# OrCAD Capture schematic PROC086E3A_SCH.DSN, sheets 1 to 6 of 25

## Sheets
1 25. HARDWARE SCHEMATICS: title: HARDWARE SCHEMATICS; rev: E3A
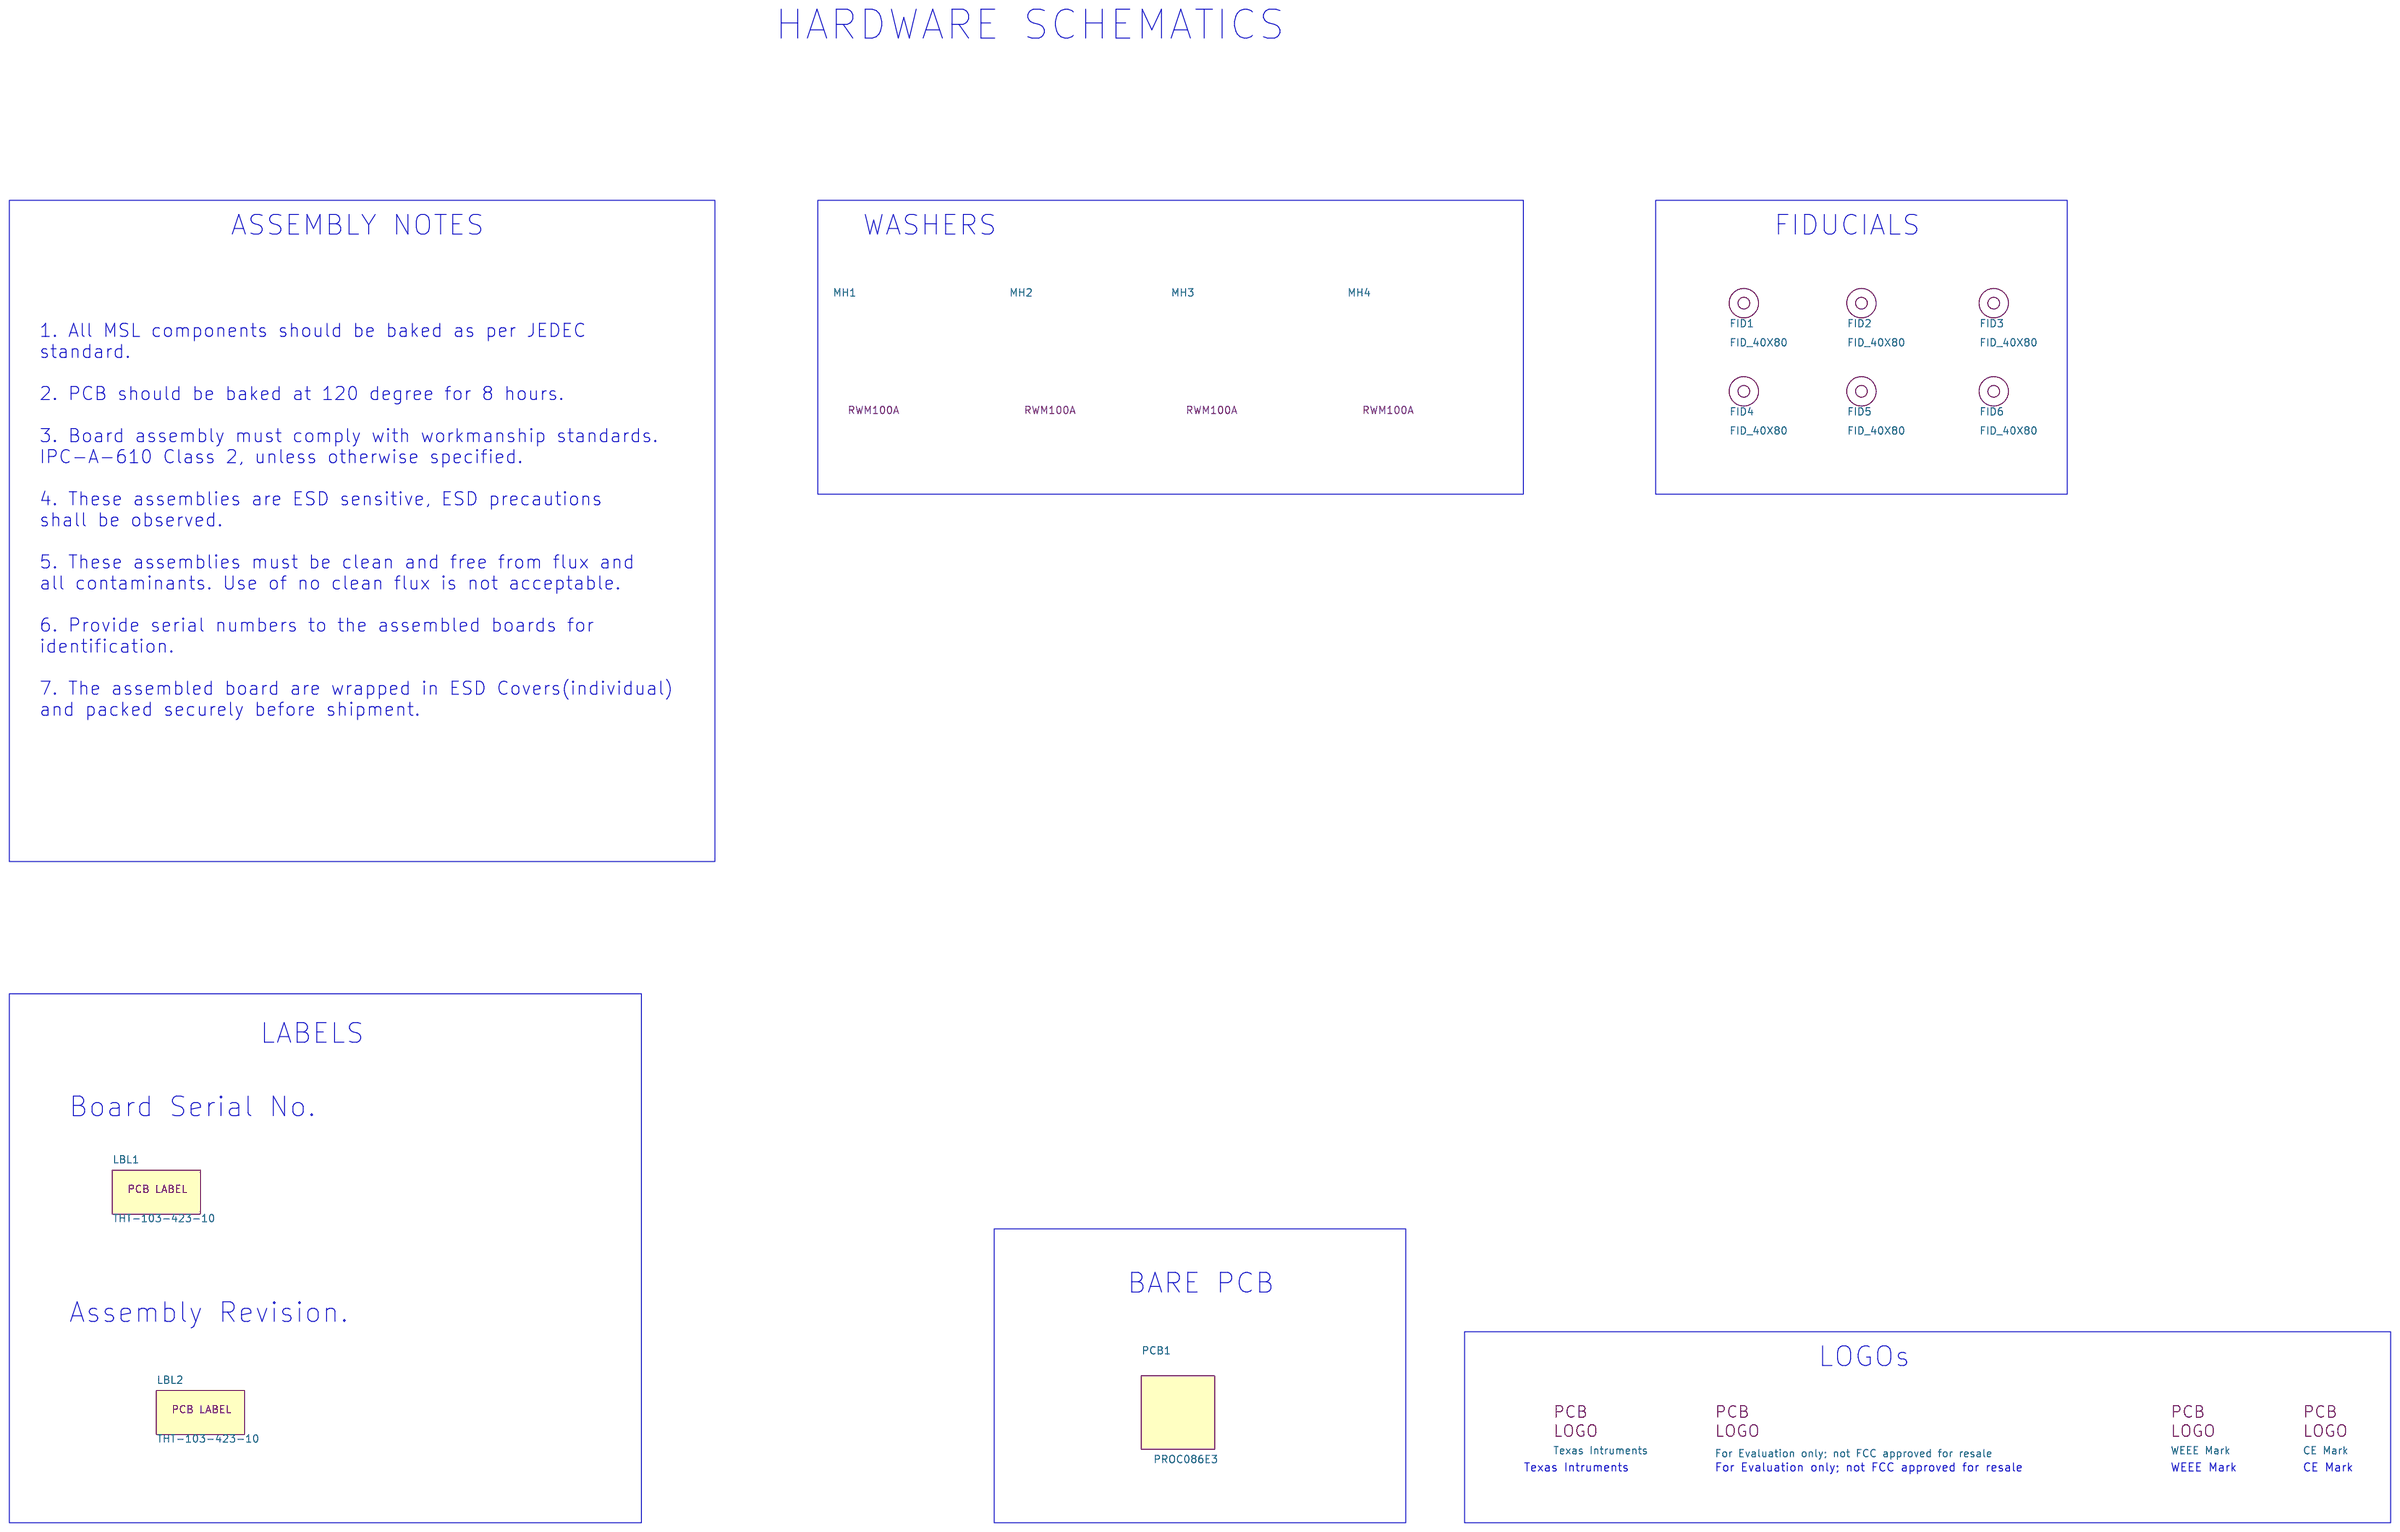
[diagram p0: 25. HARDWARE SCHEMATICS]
2 01. TABLE OF CONTENTS: title: TABLE OF CONTENTS
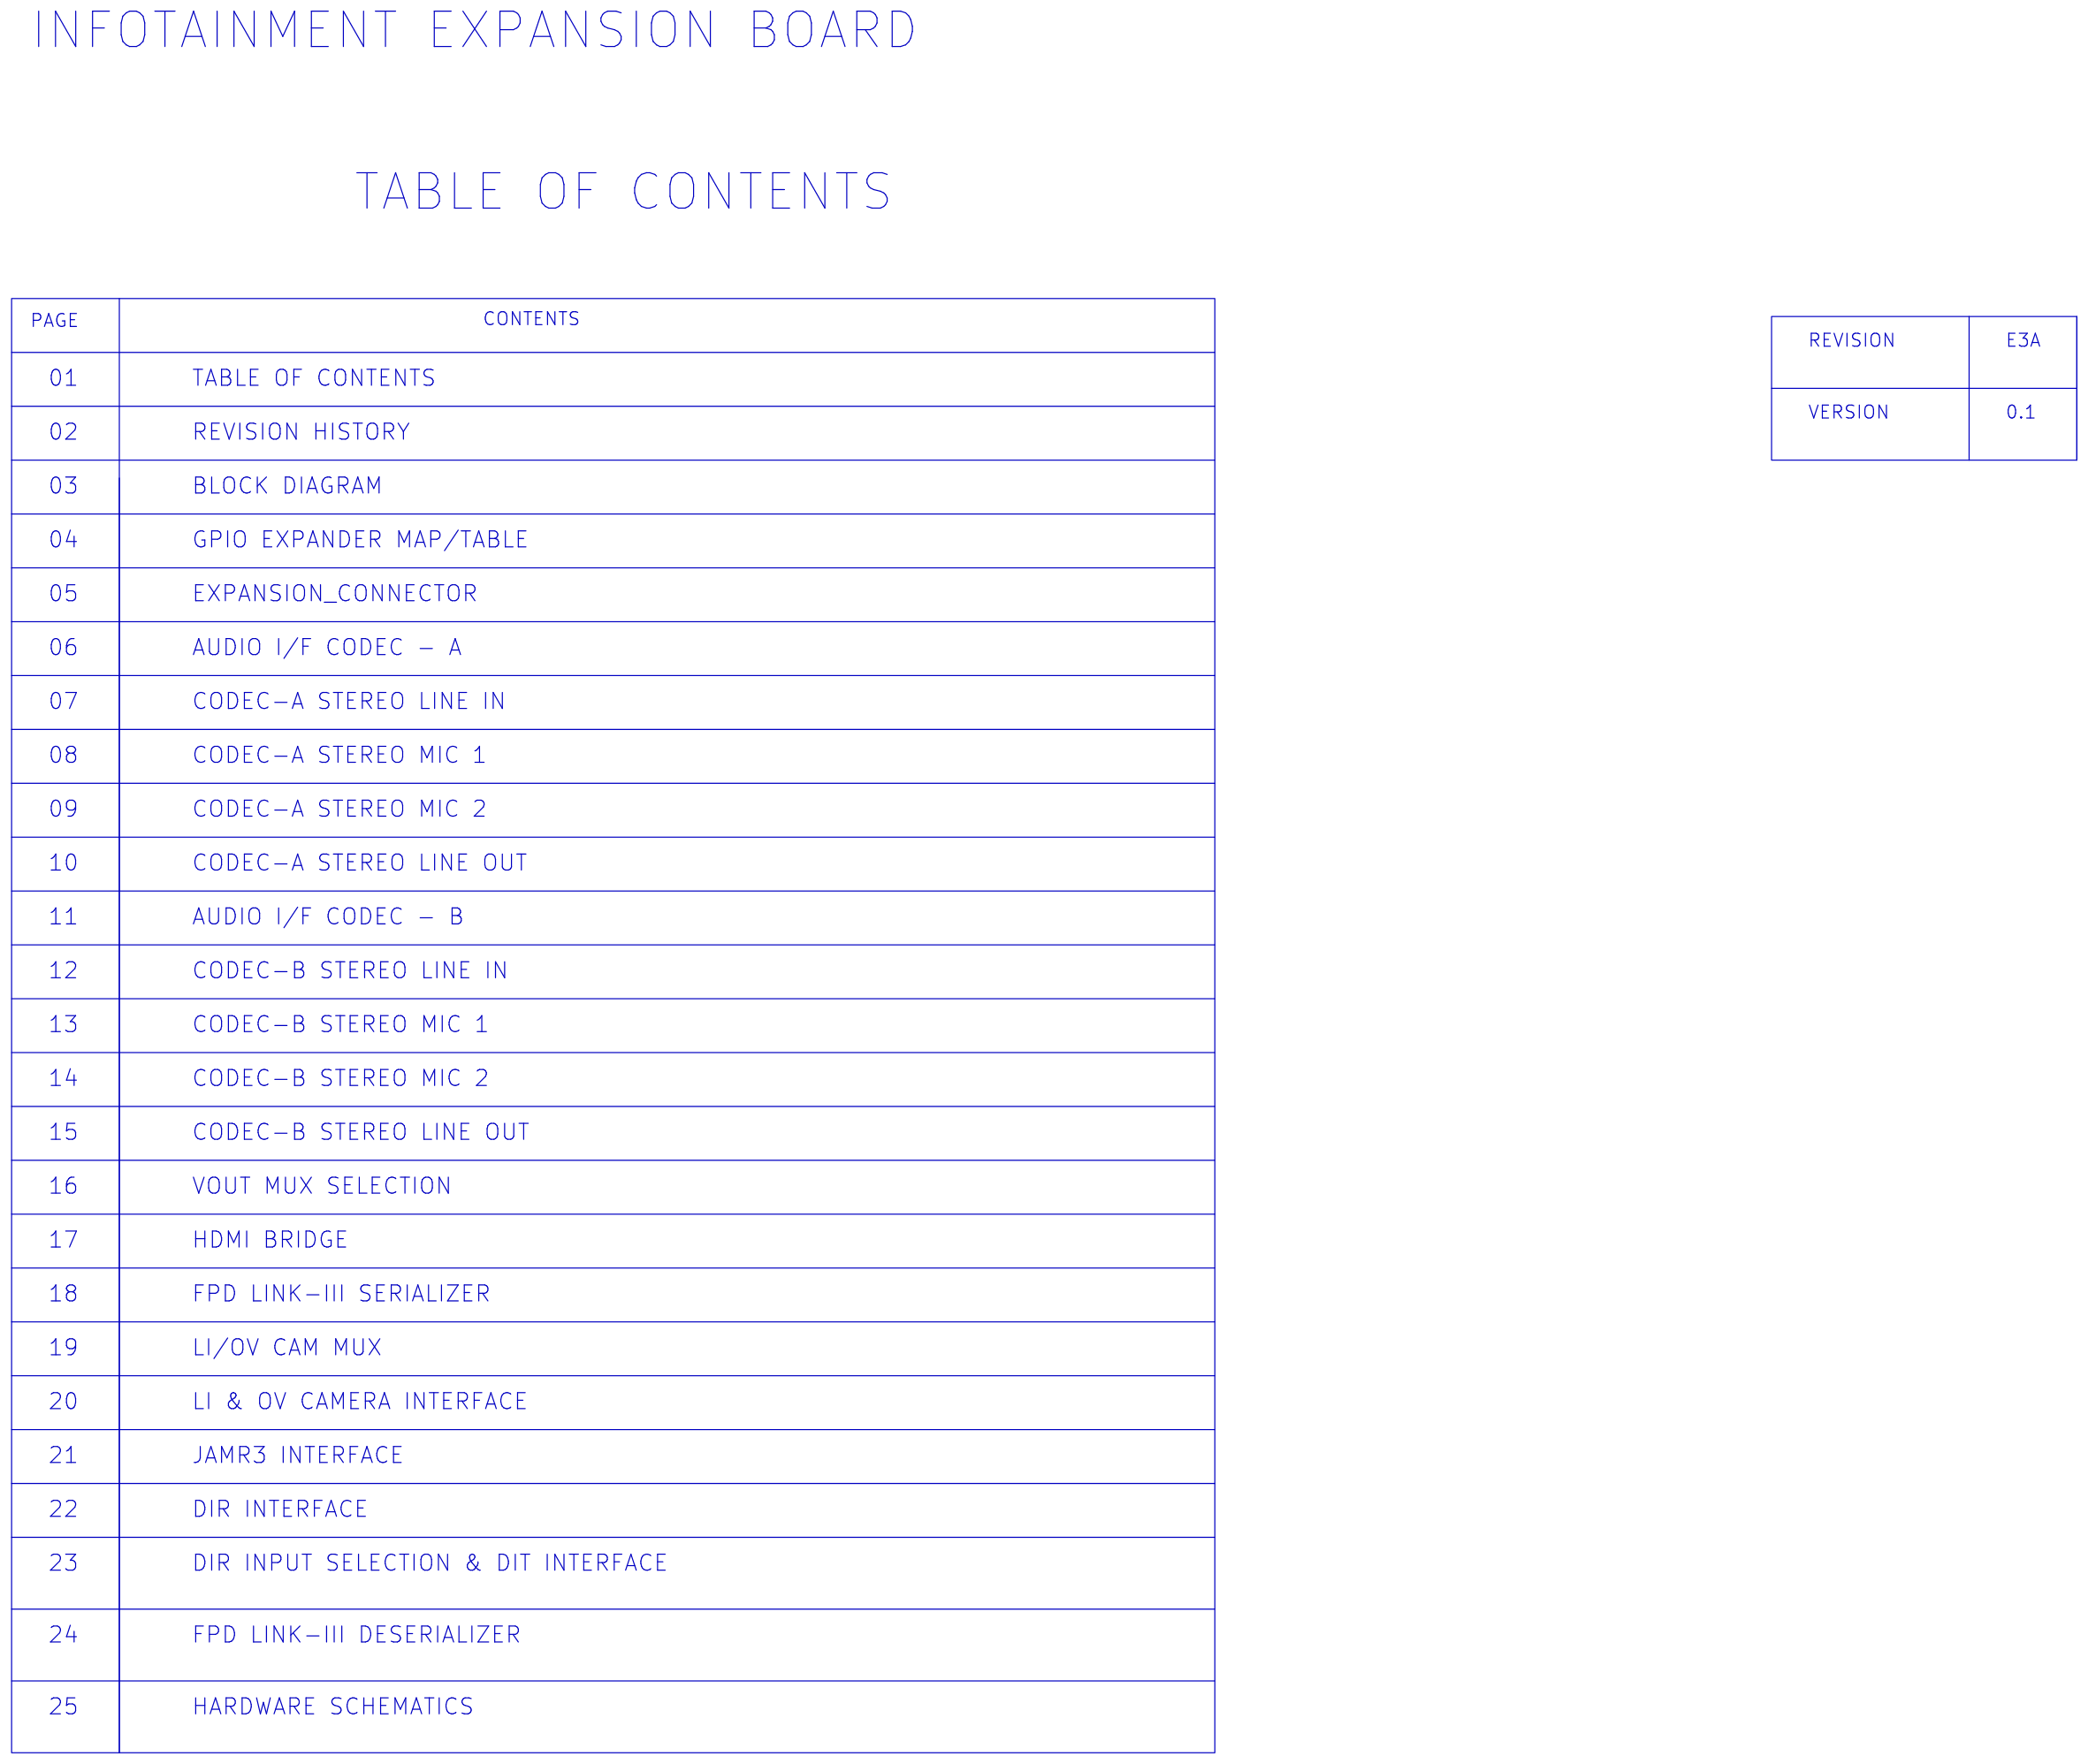
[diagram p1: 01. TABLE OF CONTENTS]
3 02. REVISION HISTORY: title: REVISION HISTORY
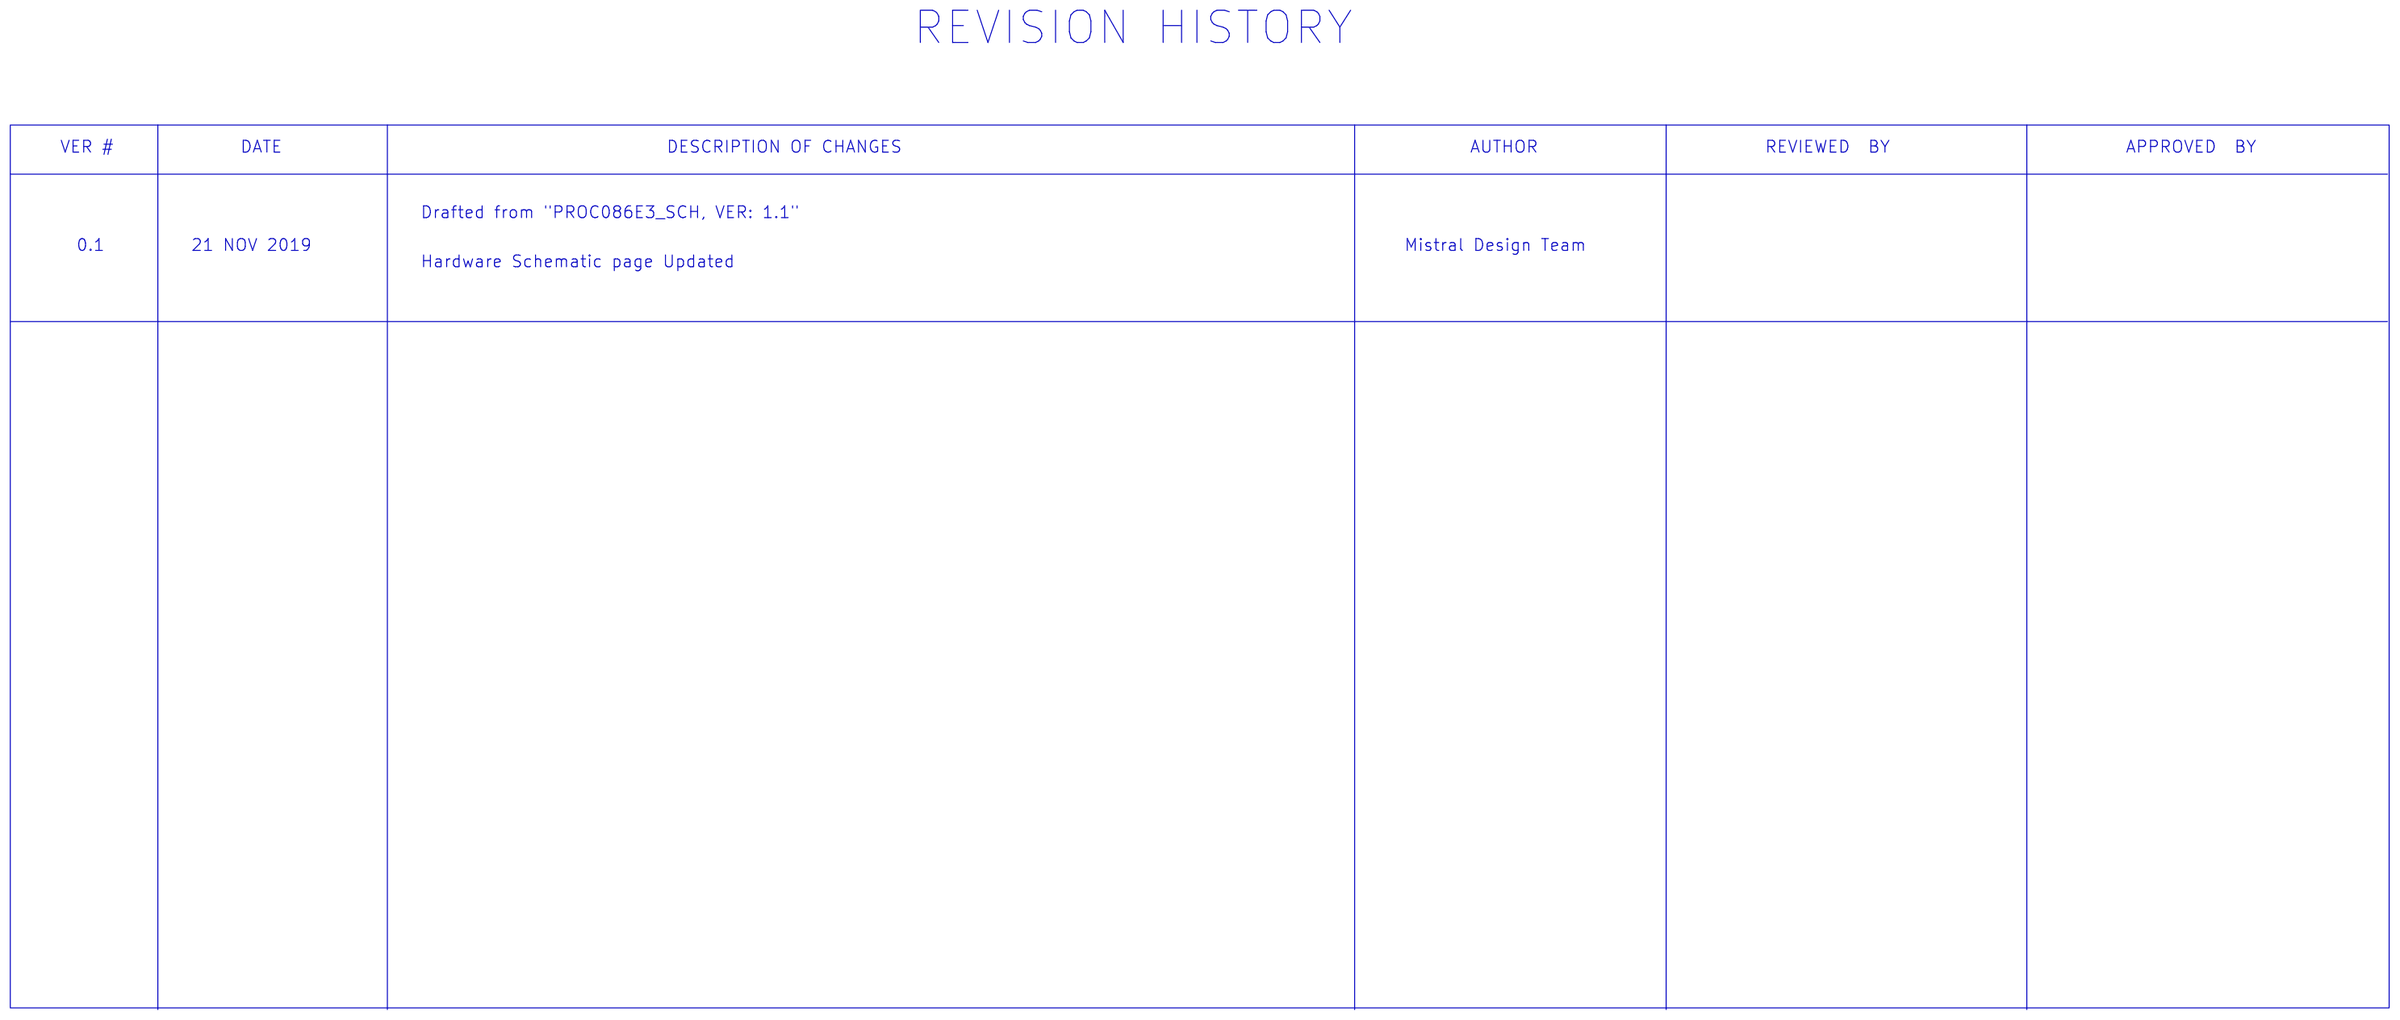
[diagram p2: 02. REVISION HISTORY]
4 03. BLOCK_DIAGRAM: title: BLOCK DIAGRAM
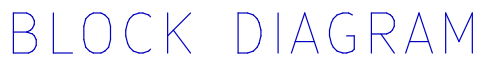
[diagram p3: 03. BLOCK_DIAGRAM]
5 05. EXPANSION_CONNECTOR: size C; title: EXPANSION CONNECTORS
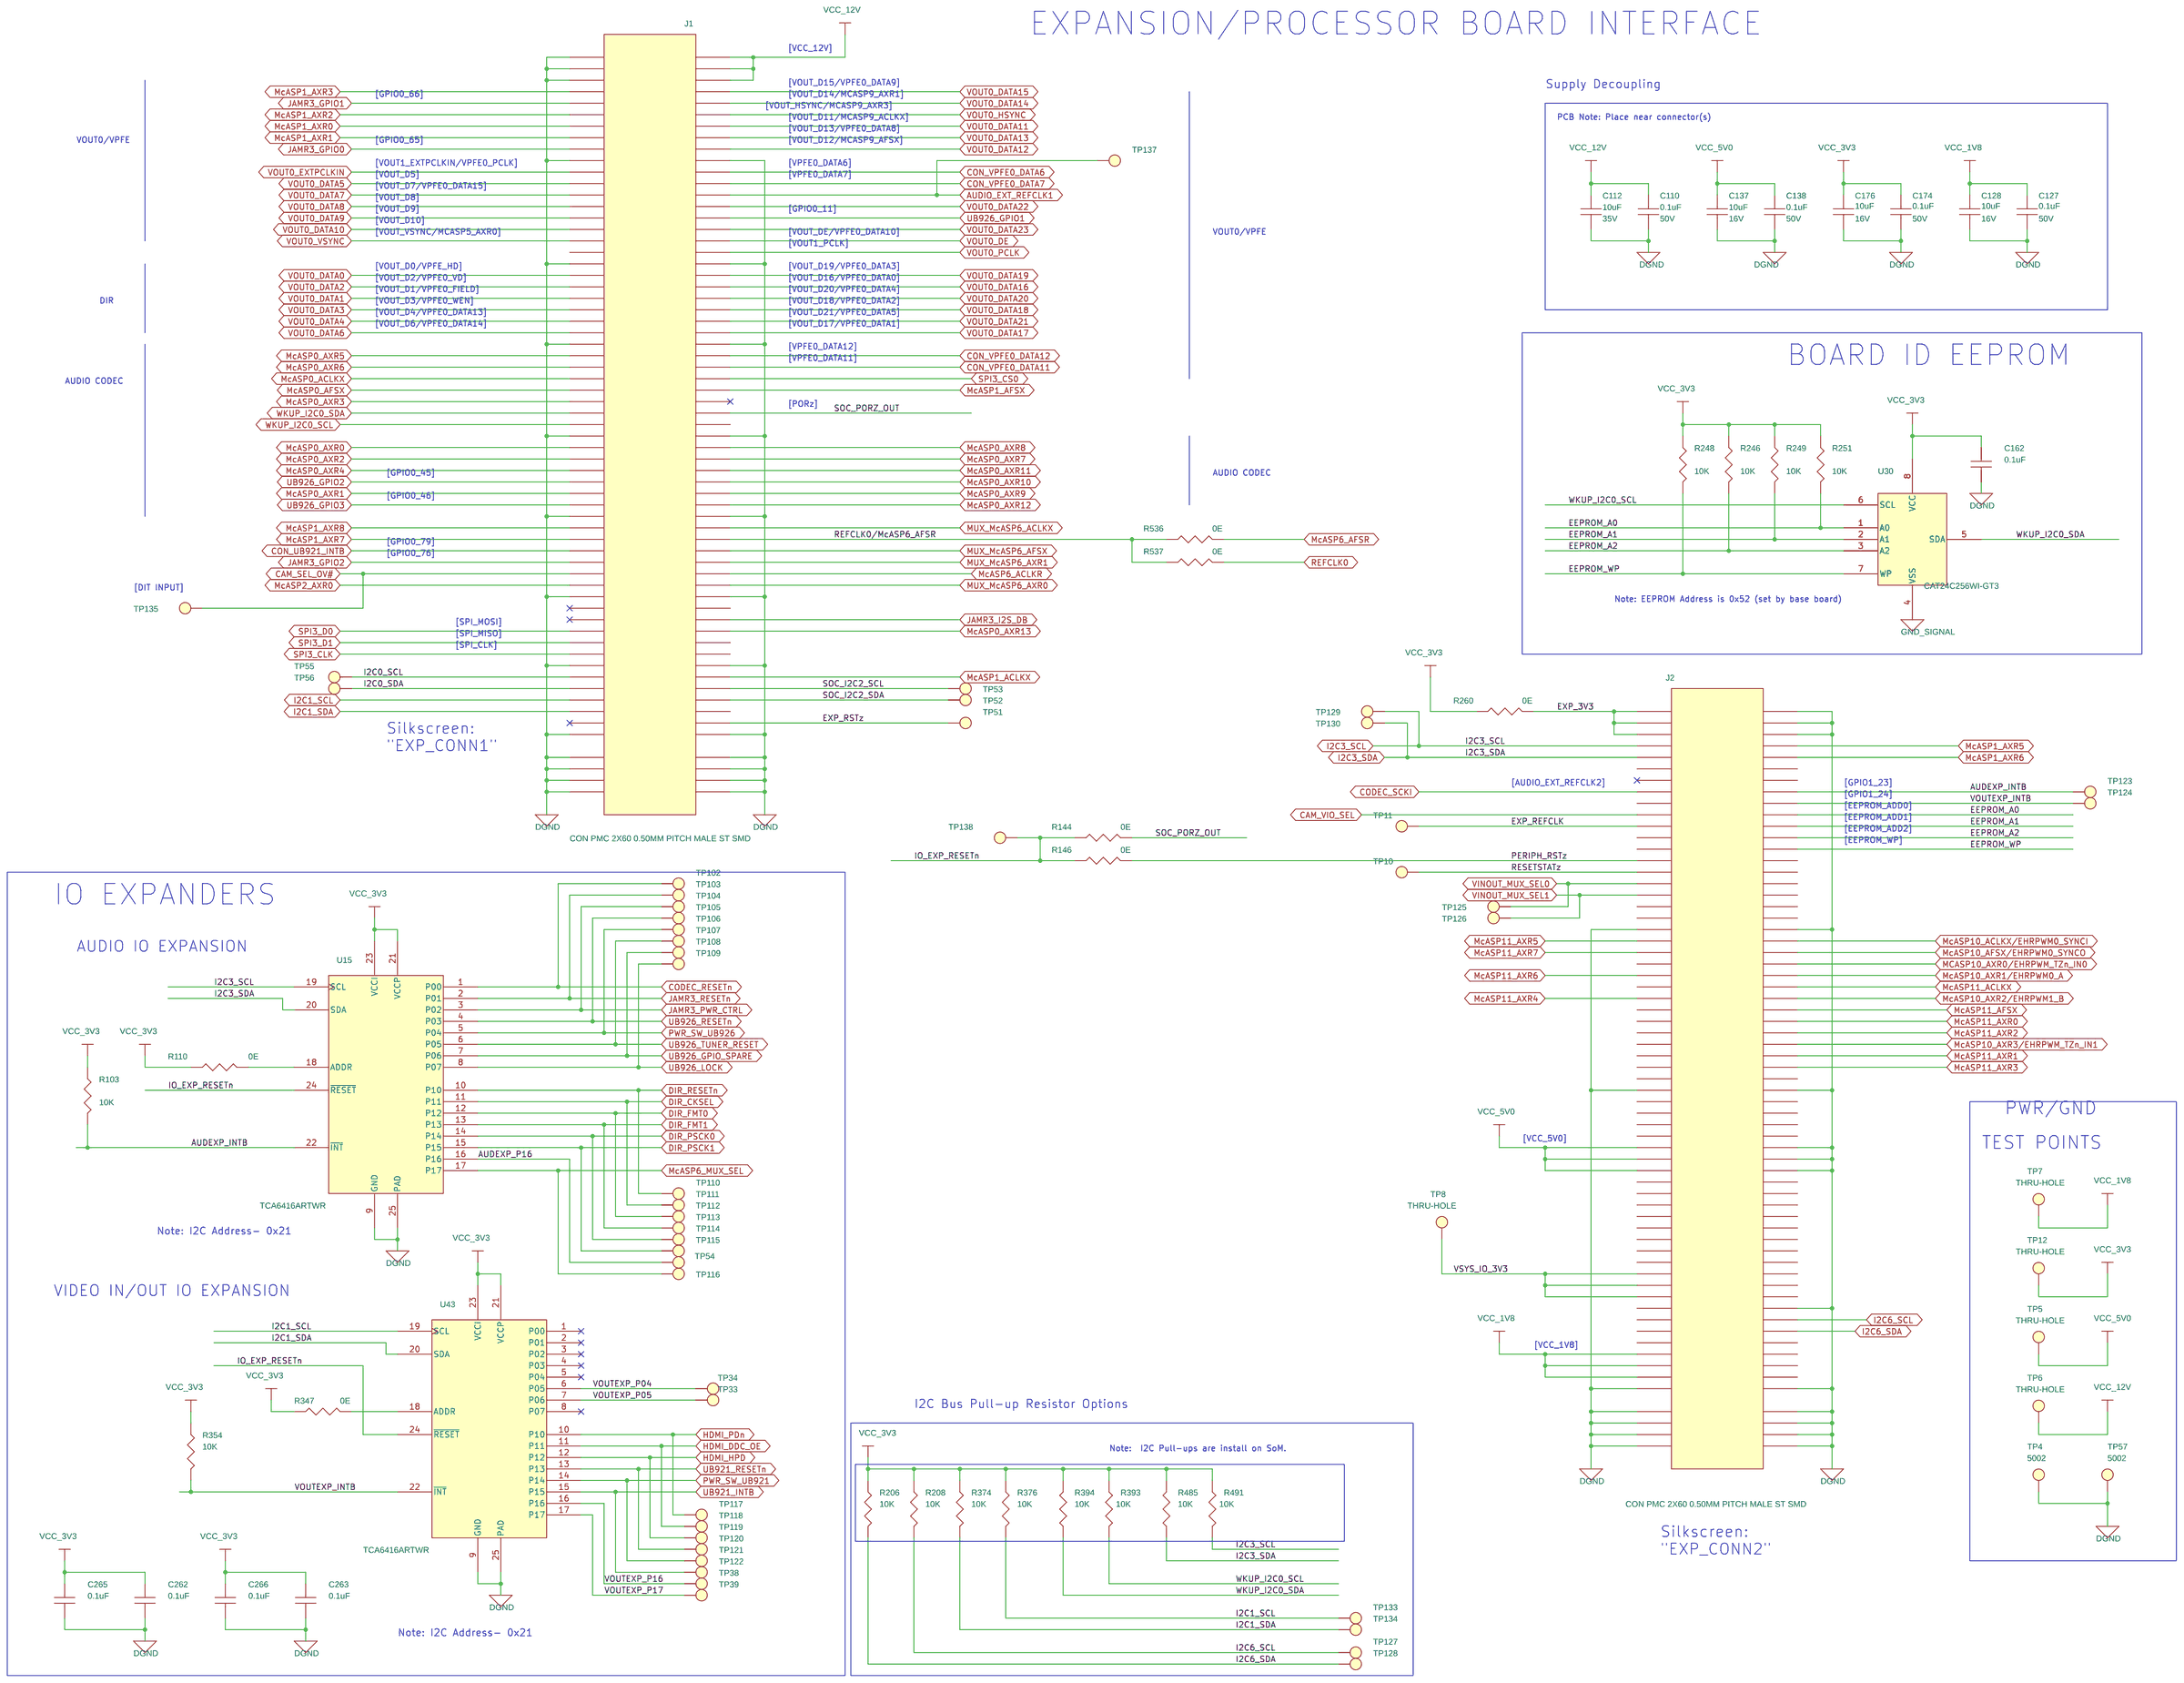
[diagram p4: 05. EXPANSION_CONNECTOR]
6 07. CODEC-A STEREO_LINE_IN: size C; title: CODEC-A STEREO LINE IN
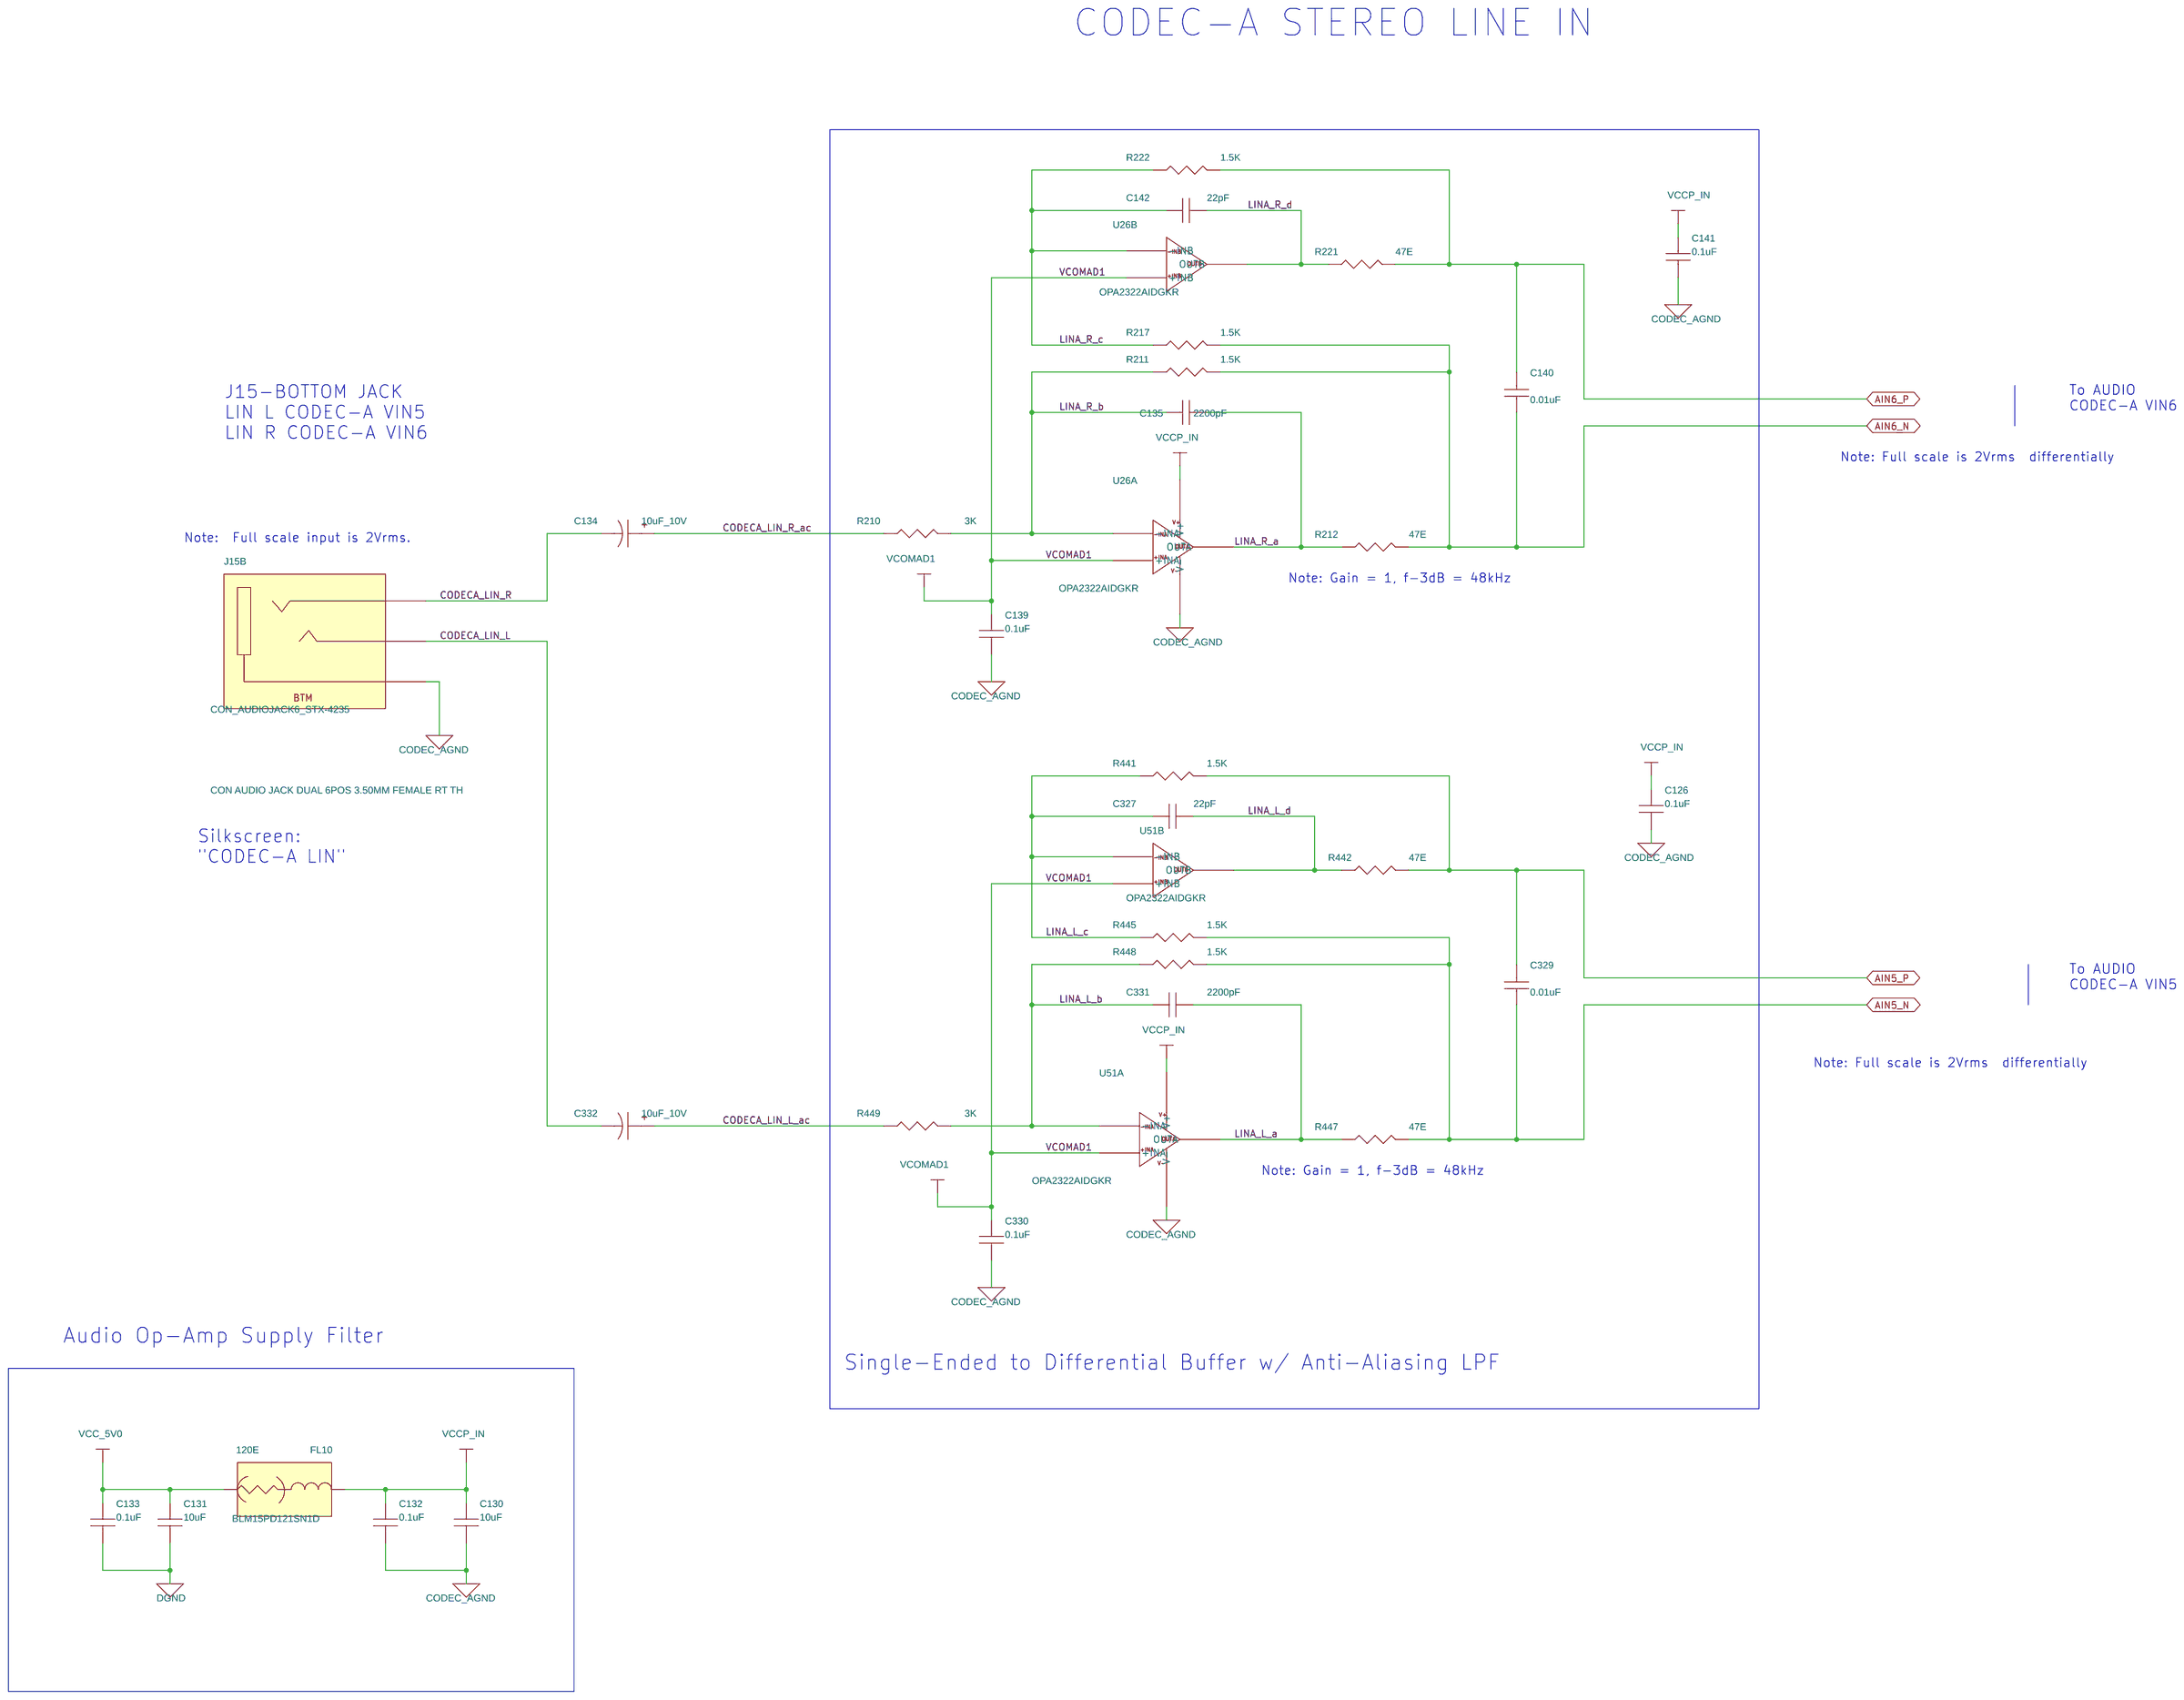
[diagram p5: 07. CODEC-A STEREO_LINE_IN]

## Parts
sheet 05. EXPANSION_CONNECTOR
C110  0.1uF  [CAP0402_0-75]
C112  10uF  [CAP1206_2]
C127  0.1uF  [CAP0402_0-75]
C128  10uF  [CAP0603_1]
C137  10uF  [CAP0603_1]
C138  0.1uF  [CAP0402_0-75]
C162  0.1uF  [CAP0402_0-75]
C174  0.1uF  [CAP0402_0-75]
C176  10uF  [CAP0603_1]
C262  0.1uF  [CAP0402_0-75]
C263  0.1uF  [CAP0402_0-75]
C265  0.1uF  [CAP0402_0-75]
C266  0.1uF  [CAP0402_0-75]
J1  CON_PMC_2X60_M  [CON_PMC2X60_QTH-60-1-D-A_P_S_S_4-4]
J2  CON_PMC_2X60_M  [CON_PMC2X60_QTH-60-1-D-A_P_S_S_4-4]
R103  10K  [RES0402_0-5]
R110  0E  [RES0402_0-5]
R144  0E  [RES0402_0-5]
R146  0E  [RES0402_0-5]
R206  10K  [RES0402_0-5]
R208  10K  [RES0402_0-5]
R246  10K  [RES0402_0-5]
R248  10K  [RES0402_0-5]
R249  10K  [RES0402_0-5]
R251  10K  [RES0402_0-5]
R260  0E  [RES0603_0-75]
R347  0E  [RES0402_0-5]
R354  10K  [RES0402_0-5]
R374  10K  [RES0402_0-5]
R376  10K  [RES0402_0-5]
R393  10K  [RES0402_0-5]
R394  10K  [RES0402_0-5]
R485  10K  [RES0402_0-5]
R491  10K  [RES0402_0-5]
R536  0E  [RES0603_0-75]
R537  0E  [RES0603_0-75]
TP4  5002  [TP_CIR67D40_TH_4-6]
TP5  THRU HOLE  [TP_40X65]
TP6  THRU HOLE  [TP_40X65]
TP7  THRU HOLE  [TP_40X65]
TP8  THRU HOLE  [TP_40X65]
TP10  TP40_SMD  [TP40_SMD]
TP11  TP40_SMD  [TP40_SMD]
TP12  THRU HOLE  [TP_40X65]
TP33  TP40_SMD  [TP40_SMD]
TP34  TP40_SMD  [TP40_SMD]
TP38  TP40_SMD  [TP40_SMD]
TP39  TP40_SMD  [TP40_SMD]
TP51  TP40_SMD  [TP40_SMD]
TP52  TP40_SMD  [TP40_SMD]
TP53  TP40_SMD  [TP40_SMD]
TP54  TP40_SMD  [TP40_SMD]
TP55  TP40_SMD  [TP40_SMD]
TP56  TP40_SMD  [TP40_SMD]
TP57  5002  [TP_CIR67D40_TH_4-6]
TP102  TP20_SMD  [TP20_SMD]
TP103  TP20_SMD  [TP20_SMD]
TP104  TP20_SMD  [TP20_SMD]
TP105  TP20_SMD  [TP20_SMD]
TP106  TP20_SMD  [TP20_SMD]
TP107  TP20_SMD  [TP20_SMD]
TP108  TP20_SMD  [TP20_SMD]
TP109  TP20_SMD  [TP20_SMD]
TP110  TP20_SMD  [TP20_SMD]
TP111  TP20_SMD  [TP20_SMD]
TP112  TP20_SMD  [TP20_SMD]
TP113  TP20_SMD  [TP20_SMD]
TP114  TP20_SMD  [TP20_SMD]
TP115  TP20_SMD  [TP20_SMD]
TP116  TP20_SMD  [TP20_SMD]
TP117  TP20_SMD  [TP20_SMD]
TP118  TP20_SMD  [TP20_SMD]
TP119  TP20_SMD  [TP20_SMD]
TP120  TP20_SMD  [TP20_SMD]
TP121  TP20_SMD  [TP20_SMD]
TP122  TP20_SMD  [TP20_SMD]
TP123  TP20_SMD  [TP20_SMD]
TP124  TP20_SMD  [TP20_SMD]
TP125  TP20_SMD  [TP20_SMD]
TP126  TP20_SMD  [TP20_SMD]
TP127  TP20_SMD  [TP20_SMD]
TP128  TP20_SMD  [TP20_SMD]
TP129  TP20_SMD  [TP20_SMD]
TP130  TP20_SMD  [TP20_SMD]
TP133  TP20_SMD  [TP20_SMD]
TP134  TP20_SMD  [TP20_SMD]
TP135  TP20_SMD  [TP20_SMD]
TP137  TP20_SMD  [TP20_SMD]
TP138  TP20_SMD  [TP20_SMD]
U15  TCA6416ARTWR  [WQFN24_19-68_160X160]
U30  CAT24C256WI-GT3  [SOIC8_1-8]
U43  TCA6416ARTWR  [WQFN24_19-68_160X160]
sheet 07. CODEC-A STEREO_LINE_IN
C126  0.1uF  [CAP0402_0-75]
C130  10uF  [CAP0603_1]
C131  10uF  [CAP0603_1]
C132  0.1uF  [CAP0402_0-75]
C133  0.1uF  [CAP0402_0-75]
C134  10uF_10V  [CAPCT0805H_1]
C135  2200pF  [CAP0402_0-75]
C139  0.1uF  [CAP0402_0-75]
C140  0.01uF  [CAP0402_0-75]
C141  0.1uF  [CAP0402_0-75]
C142  22pF  [CAP0402_0-75]
C327  22pF  [CAP0402_0-75]
C329  0.01uF  [CAP0402_0-75]
C330  0.1uF  [CAP0402_0-75]
C331  2200pF  [CAP0402_0-75]
C332  10uF_10V  [CAPCT0805H_1]
FL10  120E  [EMIFIL_BLM15A_0402_0-6]
J15  CON_AUDIOJACK6_STX-4235  [CON_AV6_STX-4235-3-3_S_R_T_26]  (sections A,B)
R210  3K  [RES0402_0-5]
R211  1.5K  [RES0402_0-5]
R212  47E  [RES0402_0-5]
R217  1.5K  [RES0402_0-5]
R221  47E  [RES0402_0-5]
R222  1.5K  [RES0402_0-5]
R441  1.5K  [RES0402_0-5]
R442  47E  [RES0402_0-5]
R445  1.5K  [RES0402_0-5]
R447  47E  [RES0402_0-5]
R448  1.5K  [RES0402_0-5]
R449  3K  [RES0402_0-5]
U26  OPA2322AIDGKR  [VSSOP8_25-59_120X120_1-1]  (sections A,B)
U51  OPA2322AIDGKR  [VSSOP8_25-59_120X120_1-1]  (sections A,B)
sheet 25. HARDWARE SCHEMATICS
FID1  FID_40X80  [FID_40X80]
FID2  FID_40X80  [FID_40X80]
FID3  FID_40X80  [FID_40X80]
FID4  FID_40X80  [FID_40X80]
FID5  FID_40X80  [FID_40X80]
FID6  FID_40X80  [FID_40X80]
LBL1  THT-103-423-10  [NA]
LBL2  THT-103-423-10  [NA]
LOGO1  Texas Intruments  [TI_Stacked_Overlay_Small]
LOGO2  For Evaluation only; not FCC approved for resale  [FCC_disclaimer]
LOGO3  WEEE Mark  [TI_Stacked_Overlay_Small]
LOGO4  CE Mark  [TI_Stacked_Overlay_Small]
MH1  FLAT WASHER_M3  [NA]
MH2  FLAT WASHER_M3  [NA]
MH3  FLAT WASHER_M3  [NA]
MH4  FLAT WASHER_M3  [NA]
PCB1  PROC086E3

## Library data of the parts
C110 C126 C127 C132 C133 C138 C139 C141 C162 C174 C262 C263 C265 C266 C330 = CAP: CAP CERAMIC 0.1uF 50V 10% X7R 0402; Chkd/date: VASANTHA/281216; Crtd /date: CHAITHANYA/051011; Custom_Duty: 15%; Customs_HS_Code: 85322990; Distributor_name: DIGIKEY; Distributor_part_number: 445-173610-1-ND; Footprint Path: Y:\MIS_DATABASE\Library\ALTIUM_TOOL\PCB_FOOTPRINTS\Altium_Footprint_Lib.PcbLib; Height: 0.60MM; Library Path: Y:\MIS_DATABASE\Library\ALTIUM_TOOL\SCHEMATICS_PARTS\MS_DISCRETE_Library.schlib; Mfr_name: TDK CORPORATION; Mfr_part_number: C1005X7R1H104K050BE; Mistral Part No: 120011100014-R; Package: 0402; Part_type: CAPACITORS\CERAMIC; Project: VP-4000-BASE-BOARD; RoHS: RoHS; Temperature: -55°C+125°C; Tolerance: 10%; Voltage: 50V; Wattage: NA; Weight: 0.65mg; Datasheet: Y:\MIS_DATABASE\DATASHEETS\CAPACITORS\TDK_C-SER_FEB19.PDF
C112 = CAP: CAP CERAMIC 10uF 35V 10% X5R 1206; Chkd/date: MANIRAJA/160519; Crtd /date: ALVY/160519; Custom_Duty: 15%; Customs_HS_Code: 85322990; Distributor_name: DIGIKEY; Distributor_part_number: 587-2484-1-ND; Footprint Path: Y:\MIS_DATABASE\Library\ALTIUM_TOOL\PCB_FOOTPRINTS\Altium_Footprint_Lib.PcbLib; Height: 1.80MM; Library Path: Y:\MIS_DATABASE\Library\ALTIUM_TOOL\SCHEMATICS_PARTS\MS_DISCRETE_Library.schlib; Mfr_name: TAIYO YUDEN; Mfr_part_number: GMK316BJ106KL-T; Mistral Part No: 120019050012-R; Package: 1206; Part_type: CAPACITORS\CERAMIC; Project: J7ES_SOM_DUAL-LEO_PMIC; RoHS: RoHS; Temperature: -55°C+85°C; Tolerance: 10%; Voltage: 35V; Wattage: NA; Weight: 16.2mg; Datasheet: Y:\MIS_DATABASE\DATASHEETS\CAPACITORS\TY-EMKXXX-2019.PDF
C128 C130 C131 C137 C176 = CAP: CAP CERAMIC 10uF 16V 20% X6S 0603; Chkd/date: VASANTHA/170117; Crtd /date: VASANTHA/170117; Custom_Duty: 15%; Customs_HS_Code: 85322990; Distributor_name: DIGIKEY; Distributor_part_number: 490-7198-1-ND; Footprint Path: Y:\MIS_DATABASE\Library\ALTIUM_TOOL\PCB_FOOTPRINTS\Altium_Footprint_Lib.PcbLib; Height: 0.90MM; Library Path: Y:\MIS_DATABASE\Library\ALTIUM_TOOL\SCHEMATICS_PARTS\MS_DISCRETE_Library.schlib; Mfr_name: MURATA; Mfr_part_number: GRM188C81C106MA73D; Mistral Part No: 120017010004-R; Package: 0603; Part_type: CAPACITORS\CERAMIC; Project: TRMM_SMART-M_PS; RoHS: RoHS; Temperature: -55°C+105°C; Tolerance: 20%; Voltage: 16V; Wattage: NA; Weight: 6.3mg; Datasheet: Y:\MIS_DATABASE\DATASHEETS\CAPACITORS\MURATA-GXX-SER_NOV17.PDF
J1 J2 = CON_INT_60X2_M: CON PMC 2X60 0.50MM PITCH MALE ST SMD; Chkd/date: MANIRAJA/251018; Crtd /date: ALVY/251018; Custom_Duty: 24%; Customs_HS_Code: 85369090; Distributor_name: DIGIKEY; Distributor_part_number: SAM10670-ND; Footprint Path: Y:\MIS_DATABASE\Library\ALTIUM_TOOL\PCB_FOOTPRINTS\Altium_Footprint_Lib.PcbLib; Height: 4.35MM; Library Path: Y:\MIS_DATABASE\Library\ALTIUM_TOOL\SCHEMATICS_PARTS\MS_CONNECTOR_Library.schlib; Mfr_name: SAMTEC; Mfr_part_number: QTH-060-01-L-D-A-K; Mistral Part No: 150018100047-R; Package: SMD; Part_type: CONNECTOR\PMC; Project: TI_J7ES_EVM_CP; RoHS: RoHS; Temperature: -55°C+125°C; Tolerance: NA; Voltage: NA; Wattage: NA; Weight: NA; Datasheet: Y:\MIS_DATABASE\DATASHEETS\CONNECTORS\QTH-GP-SER.PDF
R103 R246 R249 R251 R354 = RESISTOR: RES 10K 1/16W 5% 0402; Chkd/date: VASANTHA/061216; Crtd /date: MAZHAR/230805; Custom_Duty: 15%; Customs_HS_Code: 85332119; Distributor_name: DIGIKEY; Distributor_part_number: 311-10KJRCT-ND; Footprint Path: Y:\MIS_DATABASE\Library\ALTIUM_TOOL\PCB_FOOTPRINTS\Altium_Footprint_Lib.PcbLib; Height: 0.40MM; Library Path: Y:\MIS_DATABASE\Library\ALTIUM_TOOL\SCHEMATICS_PARTS\MS_DISCRETE_Library.schlib; Mfr_name: YAGEO AMERICA; Mfr_part_number: RC0402JR-0710KL; Mistral Part No: 110011060021-R; Package: 0402; Part_type: RESISTORS\FIXED; Project: HSE; RoHS: RoHS; Temperature: -55°C+155°C; Tolerance: 5%; Voltage: NA; Wattage: 1/16W; Weight: 0.65mg; Datasheet: Y:\MIS_DATABASE\DATASHEETS\RESISTORS\RCXXXXL-SER_MAR18.PDF
R110 R146 R347 = RESISTOR: RES 0E 1/10W JUMPER 0402; Chkd/date: VASANTHA/061216; Crtd /date: NAVEED/201014; Custom_Duty: 15%; Customs_HS_Code: 85332119; Distributor_name: DIGIKEY; Distributor_part_number: P0.0JCT-ND; Footprint Path: Y:\MIS_DATABASE\Library\ALTIUM_TOOL\PCB_FOOTPRINTS\Altium_Footprint_Lib.PcbLib; Height: 0.40MM; IBISSP_MODLES: VALUE REPEATING 2 TIME; Library Path: Y:\MIS_DATABASE\Library\ALTIUM_TOOL\SCHEMATICS_PARTS\MS_DISCRETE_Library.schlib; Mfr_name: PANASONIC-ECG; Mfr_part_number: ERJ-2GE0R00X; Mistral Part No: 110018030052-R; Package: 0402; Part_type: RESISTORS\FIXED; Project: AEGIS POM; RoHS: RoHS; Temperature: -55°C+155°C; Tolerance: NA; Voltage: NA; Wattage: 1/10W; Weight: 0.8mg; Datasheet: Y:\MIS_DATABASE\DATASHEETS\RESISTORS\PAN-ERJSER_NOV17.PDF
R144 = RESISTOR: RES 0E 1/10W JUMPER 0402; Assembly_Instruction: DNI; Chkd/date: VASANTHA/061216; Crtd /date: NAVEED/201014; Custom_Duty: 15%; Customs_HS_Code: 85332119; Distributor_name: DIGIKEY; Distributor_part_number: P0.0JCT-ND; Footprint Path: Y:\MIS_DATABASE\Library\ALTIUM_TOOL\PCB_FOOTPRINTS\Altium_Footprint_Lib.PcbLib; Height: 0.40MM; IBISSP_MODLES: VALUE REPEATING 2 TIME; Library Path: Y:\MIS_DATABASE\Library\ALTIUM_TOOL\SCHEMATICS_PARTS\MS_DISCRETE_Library.schlib; Mfr_name: PANASONIC-ECG; Mfr_part_number: ERJ-2GE0R00X; Mistral Part No: 110018030052-R; Package: 0402; Part_type: RESISTORS\FIXED; Project: AEGIS POM; RoHS: RoHS; Temperature: -55°C+155°C; Tolerance: NA; Voltage: NA; Wattage: 1/10W; Weight: 0.8mg; Datasheet: Y:\MIS_DATABASE\DATASHEETS\RESISTORS\PAN-ERJSER_NOV17.PDF
R206 R208 R248 R374 R376 R393 R394 R485 R491 = RESISTOR: RES 10K 1/16W 5% 0402; Assembly_Instruction: DNI; Chkd/date: VASANTHA/061216; Crtd /date: MAZHAR/230805; Custom_Duty: 15%; Customs_HS_Code: 85332119; Distributor_name: DIGIKEY; Distributor_part_number: 311-10KJRCT-ND; Footprint Path: Y:\MIS_DATABASE\Library\ALTIUM_TOOL\PCB_FOOTPRINTS\Altium_Footprint_Lib.PcbLib; Height: 0.40MM; Library Path: Y:\MIS_DATABASE\Library\ALTIUM_TOOL\SCHEMATICS_PARTS\MS_DISCRETE_Library.schlib; Mfr_name: YAGEO AMERICA; Mfr_part_number: RC0402JR-0710KL; Mistral Part No: 110011060021-R; Package: 0402; Part_type: RESISTORS\FIXED; Project: HSE; RoHS: RoHS; Temperature: -55°C+155°C; Tolerance: 5%; Voltage: NA; Wattage: 1/16W; Weight: 0.65mg; Datasheet: Y:\MIS_DATABASE\DATASHEETS\RESISTORS\RCXXXXL-SER_MAR18.PDF
R260 R536 R537 = RESISTOR: RES 0E 1/4W JUMPER 0603 (HP); Chkd/date: USMAN/170112; Crtd /date: CHAITHANYA/170112; Custom_Duty: 15%; Customs_HS_Code: 85332119; Distributor_name: DIGIKEY; Distributor_part_number: 541-0.0SBCT-ND; Footprint Path: Y:\MIS_DATABASE\Library\ALTIUM_TOOL\PCB_FOOTPRINTS\Altium_Footprint_Lib.PcbLib; Height: 0.55MM; Library Path: Y:\MIS_DATABASE\Library\ALTIUM_TOOL\SCHEMATICS_PARTS\MS_DISCRETE_Library.schlib; Mfr_name: VISHAY; Mfr_part_number: CRCW06030000Z0EAHP; Mistral Part No: 110012010013-R; Package: 0603; Part_type: RESISTORS\FIXED; Project: NA10NG; Remarks: This part is pulse proof, high power; RoHS: RoHS; Temperature: -55°C+155°C; Tolerance: NA; Voltage: NA; Wattage: 1/4 W; Weight: 2mg; Datasheet: Y:\MIS_DATABASE\DATASHEETS\RESISTORS\CRCWXXX-HP_SEP16.PDF
TP4 TP57 = TESTPOINT: ACCESSORIE PC TEST POINT; Chkd/date: VASANTHA/121216; Crtd /date: MANIRAJA/121216; Custom_Duty: NA; Customs_HS_Code: NA; Distributor_name: DIGIKEY; Distributor_part_number: 36-5002-ND; Footprint Path: Y:\MIS_DATABASE\Library\ALTIUM_TOOL\PCB_FOOTPRINTS\Altium_Footprint_Lib.PcbLib; Height: 4.57MM; Library Path: Y:\MIS_DATABASE\Library\ALTIUM_TOOL\SCHEMATICS_PARTS\MS_DISCRETE_Library.schlib; Mfr_name: KEYSTONE; Mistral Part No: 160016120008-R; Package: NA; Part_type: ACCESSORIES; Project: EPOS_EVM; RoHS: RoHS; Temperature: NA; Tolerance: NA; Voltage: NA; Wattage: NA; Weight: NA; Datasheet: Y:\MIS_DATABASE\DATASHEETS\MISC\ACCESSORIES\5002.PDF
TP5-TP8 TP12 = TESTPOINT: TESTPOINT 1.0MM DRILL PTH; Chkd/date: MAZHAR/271211; Crtd /date: SHREESHAIL/041005; Distributor_name: NA; Distributor_part_number: NA; Height: NA; Mfr_name: LOCAL; Mistral Part No: 130009030938; Package: THRU-HOLE; Project: HSE; Datasheet: NA
TP10 TP11 TP33 TP34 TP38 TP39 TP51-TP56 = TESTPOINT: TESTPOINT CIR 40 SMD; Chkd/date: MAZHAR/190505; Crtd /date: MAZHAR/190505; Distributor_name: NA; Distributor_part_number: NA; Footprint Path: Y:\MIS_DATABASE\Library\ALTIUM_TOOL\PCB_FOOTPRINTS\Altium_Footprint_Lib.PcbLib; Height: NA; Library Path: Y:\MIS_DATABASE\Library\ALTIUM_TOOL\SCHEMATICS_PARTS\MS_DISCRETE_Library.schlib; MECHANICAL 3D STEP FILE: NA; Mfr_name: LOCAL; Mistral Part No: 130009030933; Package: SMD; Project: RAINIER-3; RoHS: NA; Temperature: NA; Tolerance: NA; Voltage: NA; Wattage: NA; Weight: NA; Datasheet: NA
TP102-TP130 TP133-TP135 TP137 TP138 = TESTPOINT: TESTPOINT CIR 20 SMD; Chkd/date: SHREESHAIL/171006; Crtd /date: MAZHAR/171006; Custom_Duty: NA; Customs_HS_Code: NA; Distributor_name: NA; Distributor_part_number: NA; Footprint Path: Y:\MIS_DATABASE\Library\ALTIUM_TOOL\PCB_FOOTPRINTS\Altium_Footprint_Lib.PcbLib; Height: NA; Library Path: Y:\MIS_DATABASE\Library\ALTIUM_TOOL\SCHEMATICS_PARTS\MS_DISCRETE_Library.schlib; MECHANICAL 3D STEP FILE: NA; Mfr_name: LOCAL; Mistral Part No: NA; Package: SMD; Project: BT MODULE_CSRBC04; RoHS: NA; Temperature: NA; Tolerance: NA; Voltage: NA; Wattage: NA; Weight: NA; Datasheet: NA
U15 U43 = TCA6416ARTWR_WQFN24: IC I2C I/O EXPANDER 16Bit WQFN24; Chkd/date: VASANTHA/011016; Crtd /date: VASANTHA/011016; Custom_Duty: 15%; Customs_HS_Code: 85423100; Distributor_name: DIGIKEY; Distributor_part_number: 296-24826-1-ND; Height: 0.80MM; Mfr_name: TEXAS INSTRUMENTS; Mistral Part No: 141016100001-R; Package: WQFN24; Part_type: ICS\DIGITAL\BUSTRANSCEIVER; Project: OCTBTS5200_FEM; RoHS: RoHS; Temperature: -40°C+85°C; Tolerance: NA; Voltage: NA; Wattage: NA; Weight: NA; Datasheet: Y:\MIS_DATABASE\DATASHEETS\ICS\DIGITAL\BUSTRANSCEIVER\TCA6416.PDF
U30 = CAT24C256WI-GT3_SOIC8: IC 256K I2C CMOS SERIAL EEPROM SOIC8; Chkd/date: MANIRAJA/130617; Crtd /date: MUDDU/270510; Custom_Duty: 15%; Customs_HS_Code: 85423100; Distributor_name: DIGIKEY; Distributor_part_number: CAT24C256WI-GT3-ND; Height: 1.75MM; Mfr_name: ON SEMICONDUCTOR; Mistral Part No: 141110050004-R; Package: SOIC8; Part_type: ICS\DIGITAL\MEMORY; Project: CENTAURUS; RoHS: RoHS; Temperature: -40°C+85°C; Tolerance: NA; Voltage: NA; Wattage: NA; Weight: 540mg; Datasheet: Y:\MIS_DATABASE\DATASHEETS\ICS\MEMORY\CAT24C256WI.PDF
C134 C332 = CAP_POL: CAP TANTALUM 10uF 10V 20% ESR 5E H0805; Chkd/date: MANIRAJA/091018; Crtd /date: ALVY/091018; Custom_Duty: 15%; Customs_HS_Code: 85322990; Distributor_name: DIGIKEY; Distributor_part_number: 478-11046-1-ND; Footprint Path: Y:\MIS_DATABASE\Library\ALTIUM_TOOL\PCB_FOOTPRINTS\Altium_Footprint_Lib.PcbLib; Height: 1.00MM; Library Path: Y:\MIS_DATABASE\Library\ALTIUM_TOOL\SCHEMATICS_PARTS\MS_DISCRETE_Library.schlib; Mfr_name: AVX CORPORATION; Mfr_part_number: TACH106M010XTA; Mistral Part No: 120018100018-R; Package: H0805; Part_type: CAPACITORS\TANTALUM; Project: TI_J7ES_EVM_CP; RoHS: RoHS; Temperature: -55°C+125°C; Tolerance: 20%; Voltage: 10V; Wattage: NA; Weight: 5.5mg; Datasheet: Y:\MIS_DATABASE\DATASHEETS\CAPACITORS\AVX-TAC-APR18.PDF
C135 C331 = CAP: CAP CERAMIC 2200pF 50V 5% X7R 0402; Chkd/date: MANIRAJA/030619; Crtd /date: ALVY/310519; Custom_Duty: 15%; Customs_HS_Code: 85322990; Distributor_name: DIGIKEY; Distributor_part_number: 1276-1532-1-ND; Footprint Path: Y:\MIS_DATABASE\Library\ALTIUM_TOOL\PCB_FOOTPRINTS\Altium_Footprint_Lib.PcbLib; Height: 0.55MM; Library Path: Y:\MIS_DATABASE\Library\ALTIUM_TOOL\SCHEMATICS_PARTS\MS_DISCRETE_Library.schlib; Mfr_name: SAMSUNG; Mfr_part_number: CL05B222JB5NNNC; Mistral Part No: 120013090018-R; Package: 0402; Part_type: CAPACITORS\CERAMIC; Project: J7ES_SOM_DUAL-LEO_PMIC; RoHS: RoHS; Temperature: -55°C+125°C; Tolerance: 5%; Voltage: 50V; Wattage: NA; Weight: NA; Datasheet: Y:\MIS_DATABASE\DATASHEETS\CAPACITORS\CL05B222JB5NNNC.PDF
C140 C329 = CAP: CAP CERAMIC 0.01uF 50V 10% X7R 0402; Chkd/date: SHREESHAIL/301105; Crtd /date: MAZHAR/040505; Custom_Duty: 15%; Customs_HS_Code: 85322990; Distributor_name: DIGIKEY; Distributor_part_number: 399-3066-1-ND; Footprint Path: Y:\MIS_DATABASE\Library\ALTIUM_TOOL\PCB_FOOTPRINTS\Altium_Footprint_Lib.PcbLib; Height: 0.55MM; Library Path: Y:\MIS_DATABASE\Library\ALTIUM_TOOL\SCHEMATICS_PARTS\MS_DISCRETE_Library.schlib; Mfr_name: KEMET; Mfr_part_number: C0402C103K5RACTU; Mistral Part No: 120009030025-R; Package: 0402; Part_type: CAPACITORS\CERAMIC; Project: G4_SVGA; RoHS: RoHS; Temperature: -55°C+125°C; Tolerance: 10%; Voltage: 50V; Wattage: NA; Weight: 0.65mg; Datasheet: Y:\MIS_DATABASE\DATASHEETS\CAPACITORS\KEMET-C-X7R.PDF
C142 C327 = CAP: CAP CERAMIC 22pF 50V 5% C0G(NP0) 0402; Chkd/date: MANIRAJA/060619; Crtd /date: MANIRAJA/060619; Custom_Duty: 15%; Customs_HS_Code: 85322990; Distributor_name: DIGIKEY; Distributor_part_number: 1276-1116-1-ND; Footprint Path: Y:\MIS_DATABASE\Library\ALTIUM_TOOL\PCB_FOOTPRINTS\Altium_Footprint_Lib.PcbLib; Height: 0.55MM; Library Path: Y:\MIS_DATABASE\Library\ALTIUM_TOOL\SCHEMATICS_PARTS\MS_DISCRETE_Library.schlib; Mfr_name: SAMSUNG; Mfr_part_number: CL05C220JB5NNNC; Mistral Part No: 120014100023-R; Package: 0402; Part_type: CAPACITORS\CERAMIC; Project: J7ES_SOM_DUAL-LEO_PMIC; RoHS: RoHS; Temperature: -55°C+125°C; Tolerance: 5%; Voltage: 50V; Wattage: NA; Weight: 0.65mg; Datasheet: Y:\MIS_DATABASE\DATASHEETS\CAPACITORS\CL05C220JB5NNNC.PDF
FL10 = EMIFILTER_IND: IND FERRITE BEAD CHIP 120E 1.3A 0402; Chkd/date: VASANTHA/010117; Crtd /date: CHAITHANYA/150312; Custom_Duty: 24%; Customs_HS_Code: 85437099; Distributor_name: DIGIKEY; Distributor_part_number: 490-5203-1-ND; Footprint Path: Y:\MIS_DATABASE\Library\ALTIUM_TOOL\PCB_FOOTPRINTS\Altium_Footprint_Lib.PcbLib; Height: 0.55MM; Library Path: Y:\MIS_DATABASE\Library\ALTIUM_TOOL\SCHEMATICS_PARTS\MS_FILTER_Library.schlib; Mfr_name: MURATA; Mfr_part_number: BLM15PD121SN1D; Mistral Part No: 130012030043-R; Package: 0402; Part_type: FILTER; Project: GEN_3-8; RoHS: RoHS; Temperature: -55°C+125°C; Tolerance: 25%; Voltage: NA; Wattage: NA; Weight: 0.65mg; Datasheet: Y:\MIS_DATABASE\DATASHEETS\DISCRETES\INDUCTORS\BLM15X-SER.PDF
J15 = CON_AUDIOJACK6_STX-4235-3_3: CON AUDIO JACK DUAL 6POS 3.50MM FEMALE RT TH; Chkd/date: MANIRAJA/090818; Crtd /date: ALVY/080818; Custom_Duty: 24%; Customs_HS_Code: 85369090; Distributor_name: MOUSER; Distributor_part_number: 806-STX-4235-3/3-N; Footprint Path: Y:\MIS_DATABASE\Library\ALTIUM_TOOL\PCB_FOOTPRINTS\Altium_Footprint_Lib.PcbLib; Height: 26.00MM; Library Path: Y:\MIS_DATABASE\Library\ALTIUM_TOOL\SCHEMATICS_PARTS\MS_CONNECTOR_Library.schlib; Library Ref: CON_AUDIOJACK6_STX-4235-3/3; Mfr_name: KYCON; Mfr_part_number: STX-4235-3/3-N; Mistral Part No: 150018080005-R; Package: THRU-HOLE; Part_type: CONNECTOR\JACK; Project: TI_J7ES_EVM_FUSION2_SER_CAP; RoHS: RoHS; Temperature: -25°C+85°C; Tolerance: NA; Voltage: NA; Wattage: NA; Weight: NA; Datasheet: Y:\MIS_DATABASE\DATASHEETS\CONNECTORS\STX-4235-3-3-N.PDF
R210 R449 = RESISTOR: RES 3K 1/10W 5% 0402; Chkd/date: MAZHAR/150709; Crtd /date: MAZHAR/110907; Custom_Duty: 15%; Customs_HS_Code: 85332119; Distributor_name: DIGIKEY; Distributor_part_number: P3.0KJCT-ND; Footprint Path: Y:\MIS_DATABASE\Library\ALTIUM_TOOL\PCB_FOOTPRINTS\Altium_Footprint_Lib.PcbLib; Height: 0.40MM; Library Path: Y:\MIS_DATABASE\Library\ALTIUM_TOOL\SCHEMATICS_PARTS\MS_DISCRETE_Library.schlib; Mfr_name: PANASONIC-ECG; Mfr_part_number: ERJ-2GEJ302X; Mistral Part No: 110009030764-R; Package: 0402; Part_type: RESISTORS\FIXED; Project: TELEMETRY ENCODER; RoHS: RoHS; Temperature: -55°C+155°C; Tolerance: 5%; Voltage: NA; Wattage: 1/10W; Weight: 0.8mg; Datasheet: Y:\MIS_DATABASE\DATASHEETS\RESISTORS\PAN-ERJSER_NOV17.PDF
R211 R217 R222 R441 R445 R448 = RESISTOR: RES 1.5K 1/16W 5% 0402; Chkd/date: MANIRAJA/310718; Crtd /date: BAVISH/021210; Custom_Duty: 15%; Customs_HS_Code: 85332119; Distributor_name: DIGIKEY; Distributor_part_number: 311-1.5KJRCT-ND; Footprint Path: Y:\MIS_DATABASE\Library\ALTIUM_TOOL\PCB_FOOTPRINTS\Altium_Footprint_Lib.PcbLib; Height: 0.40MM; Library Path: Y:\MIS_DATABASE\Library\ALTIUM_TOOL\SCHEMATICS_PARTS\MS_DISCRETE_Library.schlib; Mfr_name: YAGEO AMERICA; Mfr_part_number: RC0402JR-071K5L; Mistral Part No: 110010120012-R; Package: 0402; Part_type: RESISTORS\FIXED; Project: TE4; RoHS: RoHS; Temperature: -55°C+155°C; Tolerance: 5%; Voltage: NA; Wattage: 1/16W; Weight: 0.65mg; Datasheet: Y:\MIS_DATABASE\DATASHEETS\RESISTORS\RCXXXXL-SER_MAR18.PDF
R212 R221 R442 R447 = RESISTOR: RES 47E 1/16W 5% 0402; Chkd/date: MANIRAJA/250319; Crtd /date: MANIRAJA/250319; Custom_Duty: 15%; Customs_HS_Code: 85332119; Distributor_name: DIGIKEY; Distributor_part_number: 311-47JRCT-ND; Footprint Path: Y:\MIS_DATABASE\Library\ALTIUM_TOOL\PCB_FOOTPRINTS\Altium_Footprint_Lib.PcbLib; Height: 0.40MM; Library Path: Y:\MIS_DATABASE\Library\ALTIUM_TOOL\SCHEMATICS_PARTS\MS_DISCRETE_Library.schlib; Mfr_name: YAGEO AMERICA; Mfr_part_number: RC0402JR-0747RL; Mistral Part No: 110019040221-R; Package: 0402; Part_type: RESISTORS\FIXED; Project: POWERBOX; RoHS: RoHS; Temperature: -55°C+155°C; Tolerance: 5%; Voltage: NA; Wattage: 1/16W; Weight: 0.65mg; Datasheet: Y:\MIS_DATABASE\DATASHEETS\RESISTORS\RCXXXXL-SER_MAR18.PDF
U26 U51 = OPA2350UA_SOIC8: IC 20MHz 1.8V LOW NOISE RRI/O CMOS OPAMP VSSOP8; Chkd/date: MANIRAJA/161018; Crtd /date: ALVY/161018; Custom_Duty: 15%; Customs_HS_Code: 85423100; Distributor_name: DIGIKEY; Distributor_part_number: 296-41349-1-ND; Footprint Path: Y:\MIS_DATABASE\Library\ALTIUM_TOOL\PCB_FOOTPRINTS\Altium_Footprint_Lib.PcbLib; Height: 1.10MM; Library Path: Y:\MIS_DATABASE\Library\ALTIUM_TOOL\SCHEMATICS_PARTS\MS_OPAMP_Library.schlib; Mfr_name: TEXAS INSTRUMENTS; Mistral Part No: 140118100019-R; Package: VSSOP8; Part_type: ICS\ANALOG\OPAMP; Project: TI_J7ES_EVM_CP; RoHS: RoHS; Temperature: -40°C+125°C; Tolerance: NA; Voltage: NA; Wattage: NA; Weight: 26.5mg; Datasheet: Y:\MIS_DATABASE\DATASHEETS\ICS\OPAMP\OPA2322XX.PDF
FID1-FID6 = Fiducial
LBL1 LBL2 = ACCESSORY_THT-3-423-10: ACCESSORIE 1 WORKHORSE POLYSTER LABLE 0.25" X 1"; Chkd/date: MANIRAJA/270218; Crtd /date: ALVY/260218; Footprint Path: Y:\MIS_DATABASE\Library\ALTIUM_TOOL\PCB_FOOTPRINTS\Altium_Footprint_Lib.PcbLib; Library Path: Y:\MIS_DATABASE\Library\ALTIUM_TOOL\SCHEMATICS_PARTS\MS_MECHANICAL_Library.schlib; Mfr_name: BRADY; Mistral Part No: 160018020185; Part_type: ACCESSORIES; Project: TI_MAXIE_CPB
LOGO1 LOGO3 LOGO4 = TI_Logo
LOGO2 = FCC_disclaimer
MH1-MH4 = WASHER_FLAT: FLAT RETAINING WASHER FOR M3 NYLON; Chkd/date: MANIRAJA/160519; Crtd /date: ALVY/160519; Distributor_name: DIGIKEY; Distributor_part_number: RPC4978-ND; Mfr_name: ESSENTRA COMPONENTS; Mfr_part_number: RWM100A; Mistral Part No: 160019050020-R; Part_type: MECHANICAL\WASHERS; Project: J7ES_SOM_DUAL-LEO_PMIC; RoHS: RoHS; Datasheet: Y:\MIS_DATABASE\DATASHEETS\MISC\MECHANICAL\RWMXXXXA.PDF
PCB1 = ACCESSORY_PROC078: PROC086 BARE PCB REV E3; Mfr_name: ANY

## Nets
DGND: C110.2 C112.2 C126.2 C127.2 C128.2 C130.2 C131.2 C132.2 C133.2 C137.2 C138.2 C139.2 C141.2 C162.2 C174.2 C176.2 C262.2 C263.2 C265.2 C266.2 C330.2 J1.1 J1.3 J1.5 J1.19 J1.20 J1.37 J1.38 J1.51 J1.52 J1.67 J1.68 J1.81 J1.82 J1.95 J1.96 J1.107 J1.108 J1.119 J1.120 J1.121 J1.122 J1.123 J1.124 J1.125 J1.126 J1.127 J1.128 J2.1 J2.3 J2.5 J2.39 J2.40 J2.67 J2.68 J2.77 J2.79 J2.81 J2.105 J2.119 J2.120 J2.121 J2.122 J2.123 J2.124 J2.125 J2.126 J2.127 J2.128 J15.1B TP4.1(TP) TP57.1(TP) U15.9(GND) U15.25(PAD) U26.4(V-) U30.4(VSS) U43.9(GND) U43.25(PAD) U51.4(V-) ; also on sheet 7 8 9 10 11 12 13 14 15 16 17 18 19 20 21 22 23 25
VCC_1V8: C127.1 C128.1 J2.114 J2.116 J2.118 TP7.1(TP) ; also on sheet 16
VCC_3V3: C162.1 C174.1 C176.1 C262.1 C263.1 C265.1 C266.1 R103.1 R110.1 R206.1 R208.1 R246.1 R248.1 R249.1 R251.1 R260.1 R347.1 R354.1 R374.1 R376.1 R393.2 R394.2 R485.2 R491.2 TP12.1(TP) U15.21(VCCP) U15.23(VCCI) U30.8(VCC) U43.21(VCCP) U43.23(VCCI) ; also on sheet 14 15 16 17 18 19 20 21 22 23 25
VCC_5V0: C131.1 C133.1 C137.1 C138.1 FL10.2 J2.78 J2.80 J2.82 TP5.1(TP) ; also on sheet 9 14 15 17 22 23
VCC_12V: C110.1 C112.1 J1.2 J1.4 J1.6 TP6.1(TP) ; also on sheet 16 18 20
VCCP_IN: C126.1 C130.1 C132.1 C141.1 FL10.1 U26.8(V+) U51.8(V+) ; also on sheet 7 8 10 11 12 22 23
VINOUT_MUX_SEL0: J2.32 TP125.1(TP) ; also on sheet 14
VINOUT_MUX_SEL1: J2.34 TP126.1(TP) ; also on sheet 14
AIN5_N: C329.1 R445.2 R447.2 R448.2 ; also on sheet 23
AIN5_P: C329.2 R441.2 R442.2 ; also on sheet 23
AIN6_N: C140.1 R211.2 R212.2 R217.2 ; also on sheet 23
AIN6_P: C140.2 R221.2 R222.2 ; also on sheet 23
AUDEXP_INTB: J2.15 R103.2 TP123.1(TP) U15.22(~{INT})
AUDEXP_P16: TP54.1(TP) U15.16(P16)
AUDIO_EXT_REFCLK1: J1.26 TP137.1(TP) ; also on sheet 19
CAM_SEL_OV#: J1.91 TP135.1(TP) ; also on sheet 21
CAM_VIO_SEL: J2.20 ; also on sheet 17
CODEC_RESETn: TP102.1(TP) U15.1(P00) ; also on sheet 22 23
CODEC_SCKI: J2.16 ; also on sheet 23
CODECA_LIN_L: C332.2 J15.5B
CODECA_LIN_L_ac: C332.1 R449.1
CODECA_LIN_R: C134.2 J15.2B
CODECA_LIN_R_ac: C134.1 R210.1
CON_UB921_INTB: J1.87 ; also on sheet 16
CON_VPFE0_DATA6: J1.22 ; also on sheet 14
CON_VPFE0_DATA7: J1.24 ; also on sheet 14
CON_VPFE0_DATA11: J1.56 ; also on sheet 14
CON_VPFE0_DATA12: J1.54 ; also on sheet 14
DIR_CKSEL: TP111.1(TP) U15.11(P11) ; also on sheet 19
DIR_FMT0: TP112.1(TP) U15.12(P12) ; also on sheet 19
DIR_FMT1: TP113.1(TP) U15.13(P13) ; also on sheet 19
DIR_PSCK0: TP114.1(TP) U15.14(P14) ; also on sheet 19
DIR_PSCK1: TP115.1(TP) U15.15(P15) ; also on sheet 19
DIR_RESETn: TP110.1(TP) U15.10(P10) ; also on sheet 19
EEPROM_A0: J2.19 R251.2 U30.1(A0)
EEPROM_A1: J2.21 R249.2 U30.2(A1)
EEPROM_A2: J2.23 R246.2 U30.3(A2)
EEPROM_WP: J2.25 R248.2 U30.7(WP)
EXP_3V3: J2.2 J2.4 J2.6 R260.2
EXP_REFCLK: J2.22 TP11.1(TP)
EXP_RSTz: J1.118 TP51.1(TP)
HDMI_DDC_OE: TP118.1(TP) U43.11(P11) ; also on sheet 15
HDMI_HPD: TP119.1(TP) U43.12(P12) ; also on sheet 15
HDMI_PDn: TP117.1(TP) U43.10(P10) ; also on sheet 15
I2C0_SCL: J1.109 TP55.1(TP)
I2C0_SDA: J1.111 TP56.1(TP)
I2C1_SCL: J1.113 R376.2 TP133.1(TP) U43.19(SCL) ; also on sheet 15 16
I2C1_SDA: J1.115 R374.2 TP134.1(TP) U43.20(SDA) ; also on sheet 15 16
I2C3_SCL: J2.8 R491.1 TP129.1(TP) U15.19(SCL) ; also on sheet 18 20 22 23
I2C3_SDA: J2.10 R485.1 TP130.1(TP) U15.20(SDA) ; also on sheet 18 20 22 23
I2C6_SCL: J2.107 R208.2 TP127.1(TP) ; also on sheet 21
I2C6_SDA: J2.109 R206.2 TP128.1(TP) ; also on sheet 21
IO_EXP_RESETn: R144.1 R146.1 TP138.1(TP) U15.24(~{RESET}) U43.24(~{RESET})
JAMR3_GPIO0: J1.17 ; also on sheet 18
JAMR3_GPIO1: J1.9 ; also on sheet 18
JAMR3_GPIO2: J1.89 ; also on sheet 18
JAMR3_I2S_DB: J1.100 ; also on sheet 18
JAMR3_PWR_CTRL: TP104.1(TP) U15.3(P02) ; also on sheet 18
JAMR3_RESETn: TP103.1(TP) U15.2(P01) ; also on sheet 18
LINA_L_a: C331.2 R447.1 U51.1(OUTA)
LINA_L_b: C331.1 R448.1 R449.2 U51.2(-INA)
LINA_L_c: C327.1 R441.1 R445.1 U51.6(-INB)
LINA_L_d: C327.2 R442.1 U51.7(OUTB)
LINA_R_a: C135.2 R212.1 U26.1(OUTA)
LINA_R_b: C135.1 R210.2 R211.1 U26.2(-INA)
LINA_R_c: C142.1 R217.1 R222.1 U26.6(-INB)
LINA_R_d: C142.2 R221.1 U26.7(OUTB)
McASP0_ACLKX: J1.57 ; also on sheet 23
McASP0_AFSX: J1.59 ; also on sheet 22 23
McASP0_AXR0: J1.69 ; also on sheet 23
McASP0_AXR1: J1.77 ; also on sheet 23
McASP0_AXR2: J1.71 ; also on sheet 23
McASP0_AXR3: J1.61 ; also on sheet 23
McASP0_AXR4: J1.73 ; also on sheet 23
McASP0_AXR5: J1.53 ; also on sheet 23
McASP0_AXR6: J1.55 ; also on sheet 23
McASP0_AXR7: J1.72 ; also on sheet 22
McASP0_AXR8: J1.70 ; also on sheet 22
McASP0_AXR9: J1.78 ; also on sheet 22
McASP0_AXR10: J1.76 ; also on sheet 22
McASP0_AXR11: J1.74 ; also on sheet 22
McASP0_AXR12: J1.80 ; also on sheet 22
McASP0_AXR13: J1.102 ; also on sheet 22
McASP1_ACLKX: J1.110 ; also on sheet 20
McASP1_AFSX: J1.60 ; also on sheet 20
McASP1_AXR0: J1.13 ; also on sheet 20
McASP1_AXR1: J1.15 ; also on sheet 20
McASP1_AXR2: J1.11 ; also on sheet 20
McASP1_AXR3: J1.7 ; also on sheet 20
McASP1_AXR5: J2.7 ; also on sheet 20
McASP1_AXR6: J2.9 ; also on sheet 20
McASP1_AXR7: J1.85 ; also on sheet 20
McASP1_AXR8: J1.83 ; also on sheet 20
McASP2_AXR0: J1.93 ; also on sheet 25
McASP6_ACLKR: J1.92 ; also on sheet 19
McASP6_AFSR: R536.2 ; also on sheet 19
McASP6_MUX_SEL: TP116.1(TP) U15.17(P17) ; also on sheet 14
McASP10_ACLKX/EHRPWM0_SYNCI: J2.41 ; also on sheet 25
McASP10_AFSX/EHRPWM0_SYNCO: J2.43 ; also on sheet 25
MCASP10_AXR0/EHRPWM_TZn_IN0: J2.45 ; also on sheet 25
McASP10_AXR1/EHRPWM0_A: J2.47 ; also on sheet 25
McASP10_AXR2/EHRPWM1_B: J2.51 ; also on sheet 25
McASP10_AXR3/EHRPWM_TZn_IN1: J2.59 ; also on sheet 25
McASP11_ACLKX: J2.49 ; also on sheet 18
McASP11_AFSX: J2.53 ; also on sheet 18
McASP11_AXR0: J2.55 ; also on sheet 18
McASP11_AXR1: J2.61 ; also on sheet 18
McASP11_AXR2: J2.57 ; also on sheet 18
McASP11_AXR3: J2.63 ; also on sheet 18
McASP11_AXR4: J2.52 ; also on sheet 18
McASP11_AXR5: J2.42 ; also on sheet 18
McASP11_AXR6: J2.48 ; also on sheet 18
McASP11_AXR7: J2.44 ; also on sheet 18
MUX_McASP6_ACLKX: J1.84 ; also on sheet 14
MUX_McASP6_AFSX: J1.88 ; also on sheet 14
MUX_McASP6_AXR0: J1.94 ; also on sheet 14
MUX_McASP6_AXR1: J1.90 ; also on sheet 14
PERIPH_RSTz: J2.28 R146.2
PWR_SW_UB921: TP121.1(TP) U43.14(P14) ; also on sheet 16
PWR_SW_UB926: TP106.1(TP) U15.5(P04) ; also on sheet 20
REFCLK0: R537.2 ; also on sheet 23
REFCLK0/McASP6_AFSR: J1.86 R536.1 R537.1
RESETSTATz: J2.30 TP10.1(TP)
SOC_I2C2_SCL: J1.112 TP53.1(TP)
SOC_I2C2_SDA: J1.114 TP52.1(TP)
SOC_PORZ_OUT: J1.64 R144.2
SPI3_CLK: J1.105 ; also on sheet 14
SPI3_CS0: J1.58 ; also on sheet 21
SPI3_D0: J1.101 ; also on sheet 14
SPI3_D1: J1.103 ; also on sheet 14
UB921_INTB: TP122.1(TP) U43.15(P15) ; also on sheet 16
UB921_RESETn: TP120.1(TP) U43.13(P13) ; also on sheet 16
UB926_GPIO1: J1.30 ; also on sheet 20
UB926_GPIO2: J1.75 ; also on sheet 20
UB926_GPIO3: J1.79 ; also on sheet 20
UB926_GPIO_SPARE: TP108.1(TP) U15.7(P06) ; also on sheet 20
UB926_LOCK: TP109.1(TP) U15.8(P07) ; also on sheet 20
UB926_RESETn: TP105.1(TP) U15.4(P03) ; also on sheet 20
UB926_TUNER_RESET: TP107.1(TP) U15.6(P05) ; also on sheet 20
VCOMAD1: C139.1 C330.1 U26.3(+INA) U26.5(+INB) U51.3(+INA) U51.5(+INB) ; also on sheet 7 8 23
VOUT0_DATA0: J1.39 ; also on sheet 14
VOUT0_DATA1: J1.43 ; also on sheet 14
VOUT0_DATA2: J1.41 ; also on sheet 14
VOUT0_DATA3: J1.45 ; also on sheet 14
VOUT0_DATA4: J1.47 ; also on sheet 14
VOUT0_DATA5: J1.23 ; also on sheet 14
VOUT0_DATA6: J1.49 ; also on sheet 14
VOUT0_DATA7: J1.25 ; also on sheet 14
VOUT0_DATA8: J1.27 ; also on sheet 14
VOUT0_DATA9: J1.29 ; also on sheet 14
VOUT0_DATA10: J1.31 ; also on sheet 14
VOUT0_DATA11: J1.14 ; also on sheet 14
VOUT0_DATA12: J1.18 ; also on sheet 14
VOUT0_DATA13: J1.16 ; also on sheet 14
VOUT0_DATA14: J1.10 ; also on sheet 14
VOUT0_DATA15: J1.8 ; also on sheet 14
VOUT0_DATA16: J1.42 ; also on sheet 14
VOUT0_DATA17: J1.50 ; also on sheet 14
VOUT0_DATA18: J1.46 ; also on sheet 14
VOUT0_DATA19: J1.40 ; also on sheet 14
VOUT0_DATA20: J1.44 ; also on sheet 14
VOUT0_DATA21: J1.48 ; also on sheet 14
VOUT0_DATA22: J1.28 ; also on sheet 14
VOUT0_DATA23: J1.32 ; also on sheet 14
VOUT0_DE: J1.34 ; also on sheet 14
VOUT0_EXTPCLKIN: J1.21 ; also on sheet 14
VOUT0_HSYNC: J1.12 ; also on sheet 14
VOUT0_PCLK: J1.36 ; also on sheet 14
VOUT0_VSYNC: J1.33 ; also on sheet 14
VOUTEXP_INTB: J2.17 R354.2 TP124.1(TP) U43.22(~{INT})
VOUTEXP_P04: TP34.1(TP) U43.6(P05)
VOUTEXP_P05: TP33.1(TP) U43.7(P06)
VOUTEXP_P16: TP38.1(TP) U43.16(P16)
VOUTEXP_P17: TP39.1(TP) U43.17(P17)
VSYS_IO_3V3: J2.100 J2.102 J2.104 TP8.1(TP)
WKUP_I2C0_SCL: J1.65 R393.1 U30.6(SCL) ; also on sheet 18
WKUP_I2C0_SDA: J1.63 R394.1 U30.5(SDA) ; also on sheet 18
N24613389: R110.2 U15.18(ADDR)
N24805264: R347.2 U43.18(ADDR)

Not connected (* = marked no-connect by the designer): J1 35 62* 66 97* 98 99* 104 106 116 117*; J2 11 12 13 14* 18 24 26 27 29 31 33 35 36 37 38 46 50 54 56 58 60 62 64 65 66 69 70 71 72 73 74 75 76 83 84 85 86 87 88 89 90 91 92 93 94 95 96 97 98 99 101 103 106 108 110 111 112 113 115 117; U43 1(P00)* 2(P01)* 3(P02)* 4(P03)* 5(P04)* 8(P07)*

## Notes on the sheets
sheet 1
- HARDWARE SCHEMATICS
- ASSEMBLY NOTES
- WASHERS
- FIDUCIALS
- 1. All MSL components should be baked as per JEDEC
  standard.
  2. PCB should be baked at 120 degree for 8 hours.
  3. Board assembly must comply with workmanship standards.
  IPC-A-610 Class 2, unless otherwise specified.
  4. These assemblies are ESD sensitive, ESD precautions
  shall be observed.
  5. These assemblies must be clean and free from flux and
  all contaminants. Use of no clean flux is not acceptable.
  6. Provide serial numbers to the assembled boards for
  identification.
  7. The assembled board are wrapped in ESD Covers(individual)
  and packed securely before shipment.
- LABELS
- Board Serial No.
- BARE PCB
- Assembly Revision.
- LOGOs
- Texas Intruments
- For Evaluation only; not FCC approved for resale
- WEEE Mark
- CE Mark
sheet 2
- INFOTAINMENT EXPANSION BOARD
- TABLE OF CONTENTS
- PAGE
- CONTENTS
- REVISION
- E3A
- 01
- TABLE OF CONTENTS
- VERSION
- 0.1
- 02
- REVISION HISTORY
- 03
- BLOCK DIAGRAM
- 04
- GPIO EXPANDER MAP/TABLE
- 05
- EXPANSION_CONNECTOR
- 06
- AUDIO I/F CODEC - A
- 07
- CODEC-A STEREO LINE IN
- 08
- CODEC-A STEREO MIC 1
- 09
- CODEC-A STEREO MIC 2
- 10
- CODEC-A STEREO LINE OUT
- 11
- AUDIO I/F CODEC - B
- 12
- CODEC-B STEREO LINE IN
- 13
- CODEC-B STEREO MIC 1
- 14
- CODEC-B STEREO MIC 2
- 15
- CODEC-B STEREO LINE OUT
- 16
- VOUT MUX SELECTION
- 17
- HDMI BRIDGE
- 18
- FPD LINK-III SERIALIZER
- 19
- LI/OV CAM MUX
- 20
- LI & OV CAMERA INTERFACE
- 21
- JAMR3 INTERFACE
- 22
- DIR INTERFACE
- 23
- DIR INPUT SELECTION & DIT INTERFACE
- 24
- FPD LINK-III DESERIALIZER
- 25
- HARDWARE SCHEMATICS
sheet 3
- REVISION HISTORY
- VER #
- DATE
- DESCRIPTION OF CHANGES
- AUTHOR
- REVIEWED  BY
- APPROVED  BY
- Drafted from "PROC086E3_SCH, VER: 1.1"
- 0.1
- 21 NOV 2019
- Mistral Design Team
- Hardware Schematic page Updated
sheet 4
- BLOCK DIAGRAM
sheet 5
- EXPANSION/PROCESSOR BOARD INTERFACE
- [VCC_12V]
- [VOUT_D15/VPFE0_DATA9]
- Supply Decoupling
- [GPIO0_66]
- [VOUT_D14/MCASP9_AXR1]
- [VOUT_HSYNC/MCASP9_AXR3]
- [VOUT_D11/MCASP9_ACLKX]
- [VOUT_D13/VPFE0_DATA8]
- PCB Note: Place near connector(s)
- VOUT0/VPFE
- [GPIO0_65]
- [VOUT_D12/MCASP9_AFSX]
- [VOUT1_EXTPCLKIN/VPFE0_PCLK]
- [VPFE0_DATA6]
- [VOUT_D5]
- [VPFE0_DATA7]
- [VOUT_D7/VPFE0_DATA15]
- [VOUT_D8]
- [VOUT_D9]
- [GPIO0_11]
- [VOUT_D10]
- [VOUT_VSYNC/MCASP5_AXR0]
- [VOUT_DE/VPFE0_DATA10]
- VOUT0/VPFE
- [VOUT1_PCLK]
- [VOUT_D0/VPFE_HD]
- [VOUT_D2/VPFE0_VD]
- [VOUT_D16/VPFE0_DATA0]
- [VOUT_D19/VPFE0_DATA3]
- [VOUT_D1/VPFE0_FIELD]
- [VOUT_D20/VPFE0_DATA4]
- DIR
- [VOUT_D3/VPFE0_WEN]
- [VOUT_D18/VPFE0_DATA2]
- [VOUT_D4/VPFE0_DATA13]
- [VOUT_D21/VPFE0_DATA5]
- [VOUT_D6/VPFE0_DATA14]
- [VOUT_D17/VPFE0_DATA1]
- [VPFE0_DATA12]
- BOARD ID EEPROM
- [VPFE0_DATA11]
- AUDIO CODEC
- [PORz]
- [GPIO0_45]
- AUDIO CODEC
- [GPIO0_46]
- [GPIO0_79]
- [GPIO0_76]
- [DIT INPUT]
- Note: EEPROM Address is 0x52 (set by base board)
- [SPI_MOSI]
- [SPI_CLK]
- [SPI_MISO]
- Silkscreen:
  "EXP_CONN1"
- [AUDIO_EXT_REFCLK2]
- [GPIO1_23]
- [EEPROM_ADD0]
- [GPIO1_24]
- [EEPROM_ADD1]
- [EEPROM_ADD2]
- [EEPROM_WP]
- IO EXPANDERS
- AUDIO IO EXPANSION
- PWR/GND
- [VCC_5V0]
- TEST POINTS
- Note: I2C Address- 0x21
- VIDEO IN/OUT IO EXPANSION
- [VCC_1V8]
- I2C Bus Pull-up Resistor Options
- Note:  I2C Pull-ups are install on SoM.
- Silkscreen:
  "EXP_CONN2"
- Note: I2C Address- 0x21
sheet 6
- CODEC-A STEREO LINE IN
- J15-BOTTOM JACK
  LIN L CODEC-A VIN5
  LIN R CODEC-A VIN6
- To AUDIO
  CODEC-A VIN6
- Note: Full scale is 2Vrms  differentially
- Note:  Full scale input is 2Vrms.
- Note: Gain = 1, f-3dB = 48kHz
- Silkscreen:
  "CODEC-A LIN"
- To AUDIO
  CODEC-A VIN5
- Note: Full scale is 2Vrms  differentially
- Note: Gain = 1, f-3dB = 48kHz
- Audio Op-Amp Supply Filter
- Single-Ended to Differential Buffer w/ Anti-Aliasing LPF
